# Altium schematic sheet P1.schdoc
size 1117 x 863 mm; Symbol: Drawing-Symbol_A4; @Project Name: WYVERN-E; @Page Count: 1; @Update Date: 2026-08-05; @Create Date: 2026-08-05; @Schematic Name: Schematic1; @Page No: 1; @Page Name: P1; Company: EasyEDA.com; Version: V1.0; Page Size: A4; Device: Drawing-Symbol_A4; @Create Time: 14:42:15; @Update Time: 14:42:15; Border: 1; Width: 4400; Height: 3400; Region Start: 1; X Region Count: 6; Y Region Count: 4; Blade Width: 10; Title Block Position: 3; @Board Name: Board1
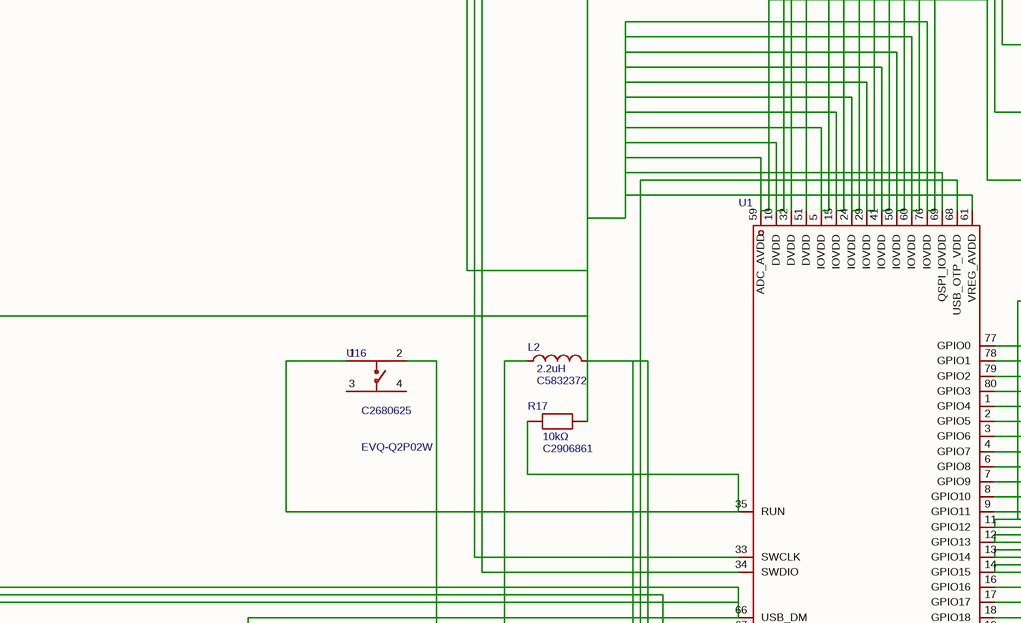
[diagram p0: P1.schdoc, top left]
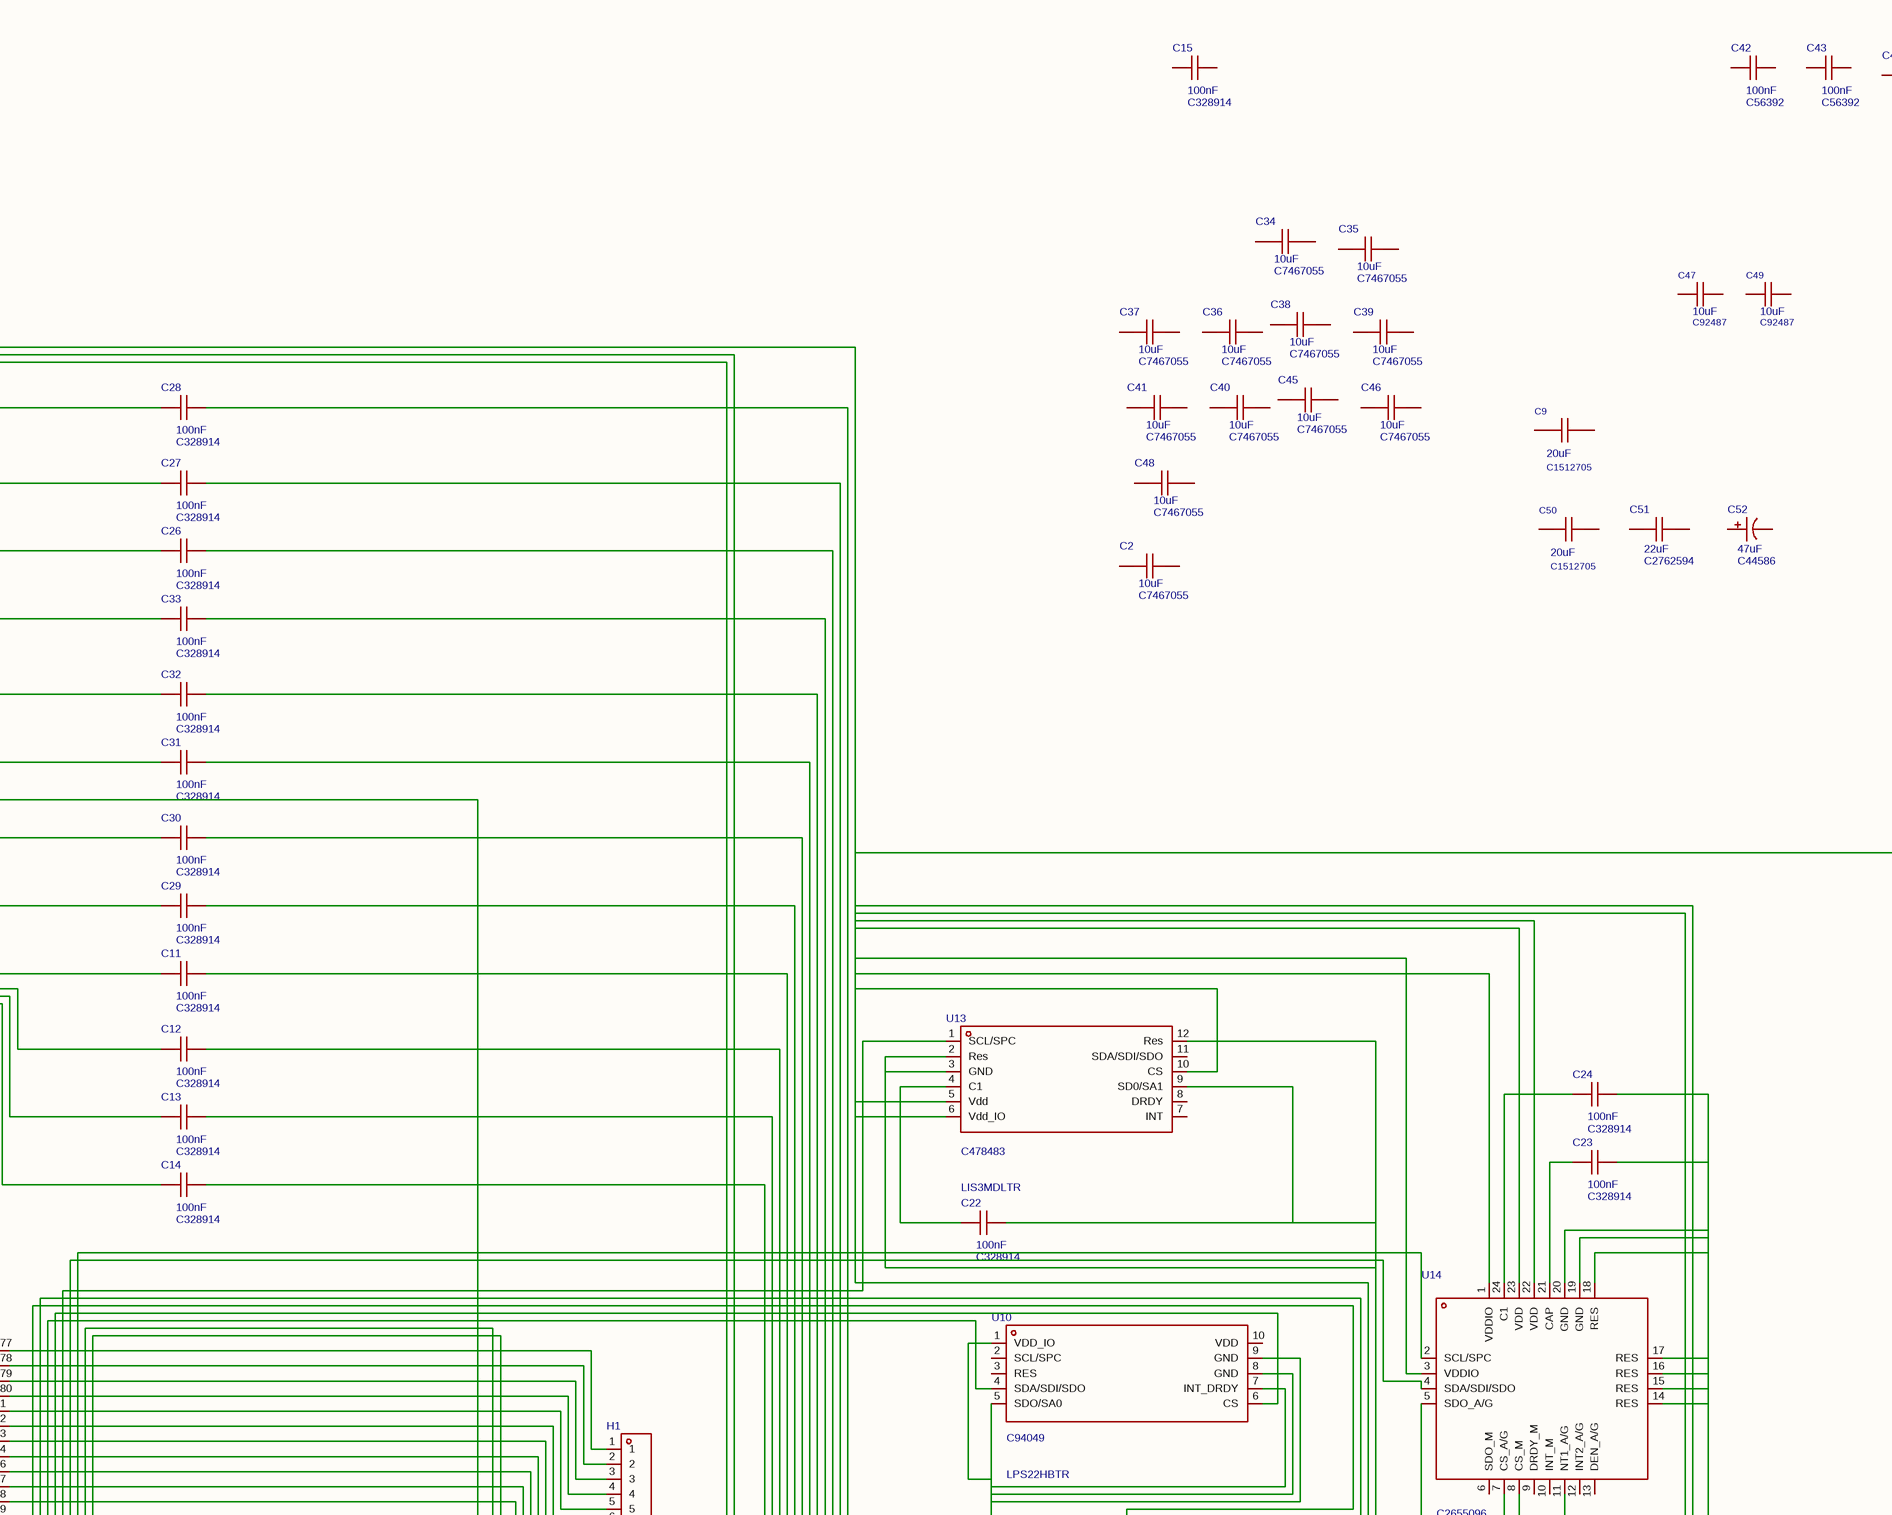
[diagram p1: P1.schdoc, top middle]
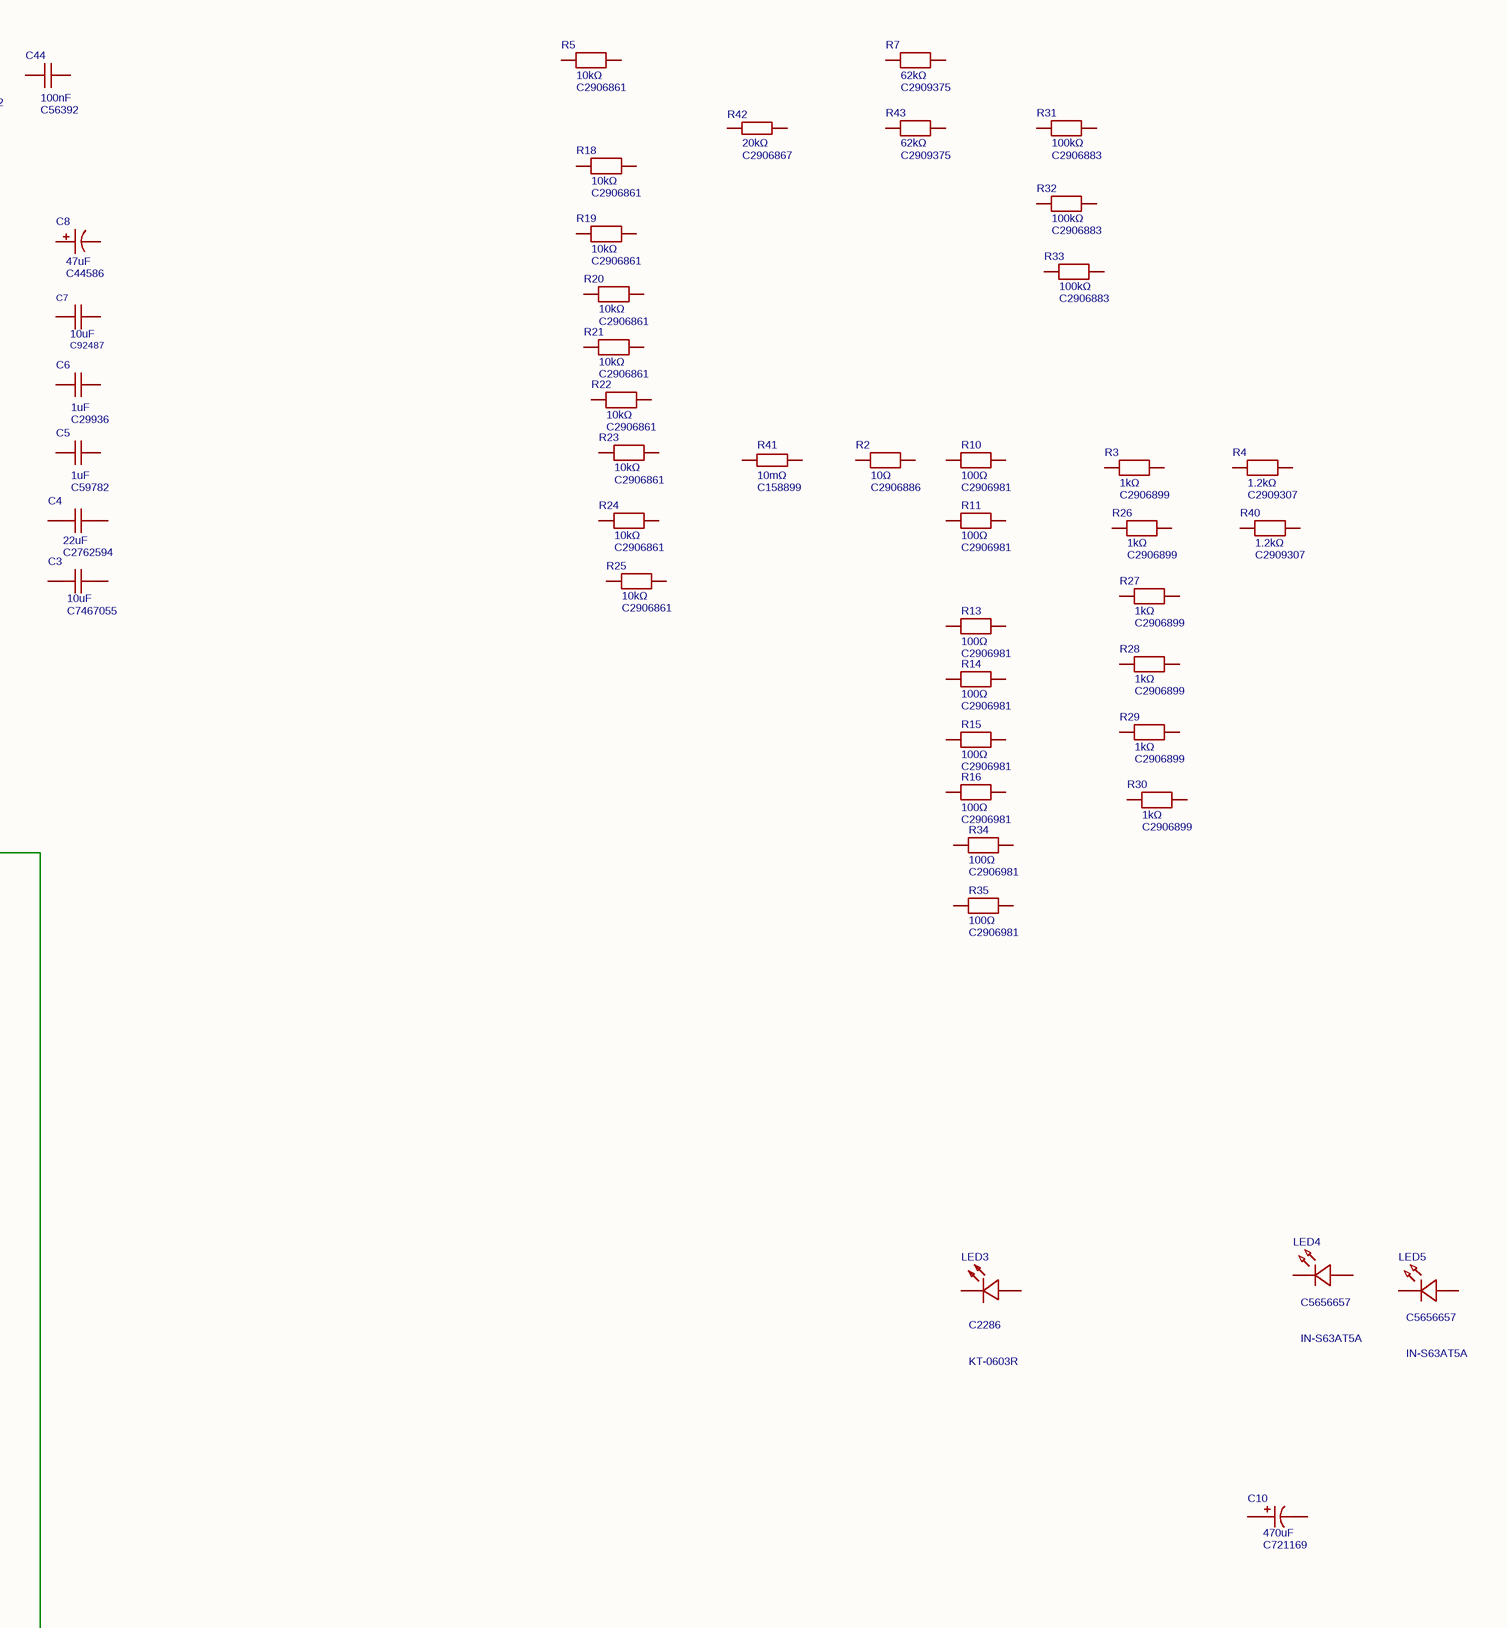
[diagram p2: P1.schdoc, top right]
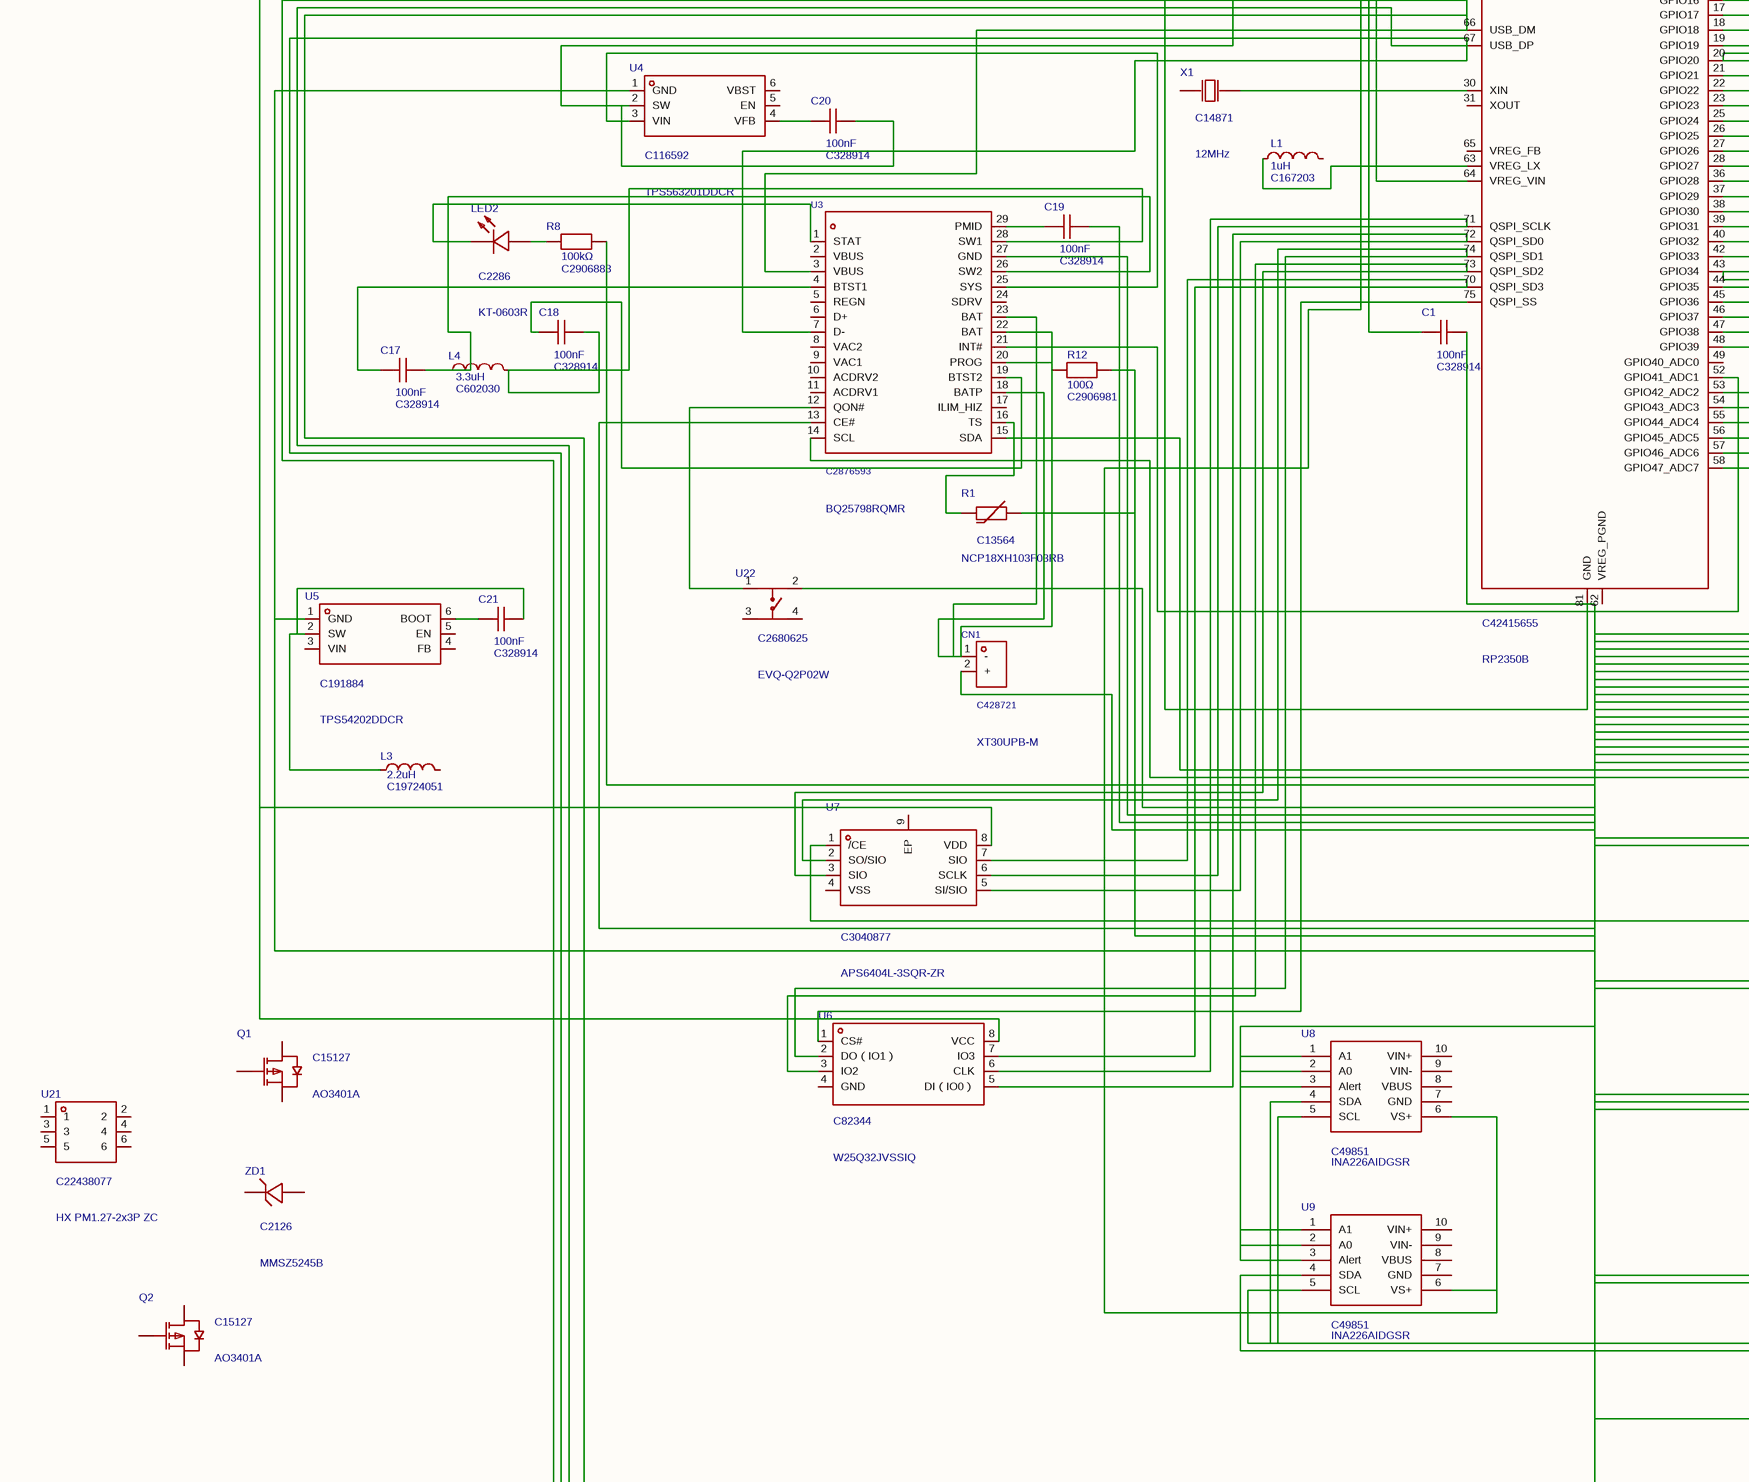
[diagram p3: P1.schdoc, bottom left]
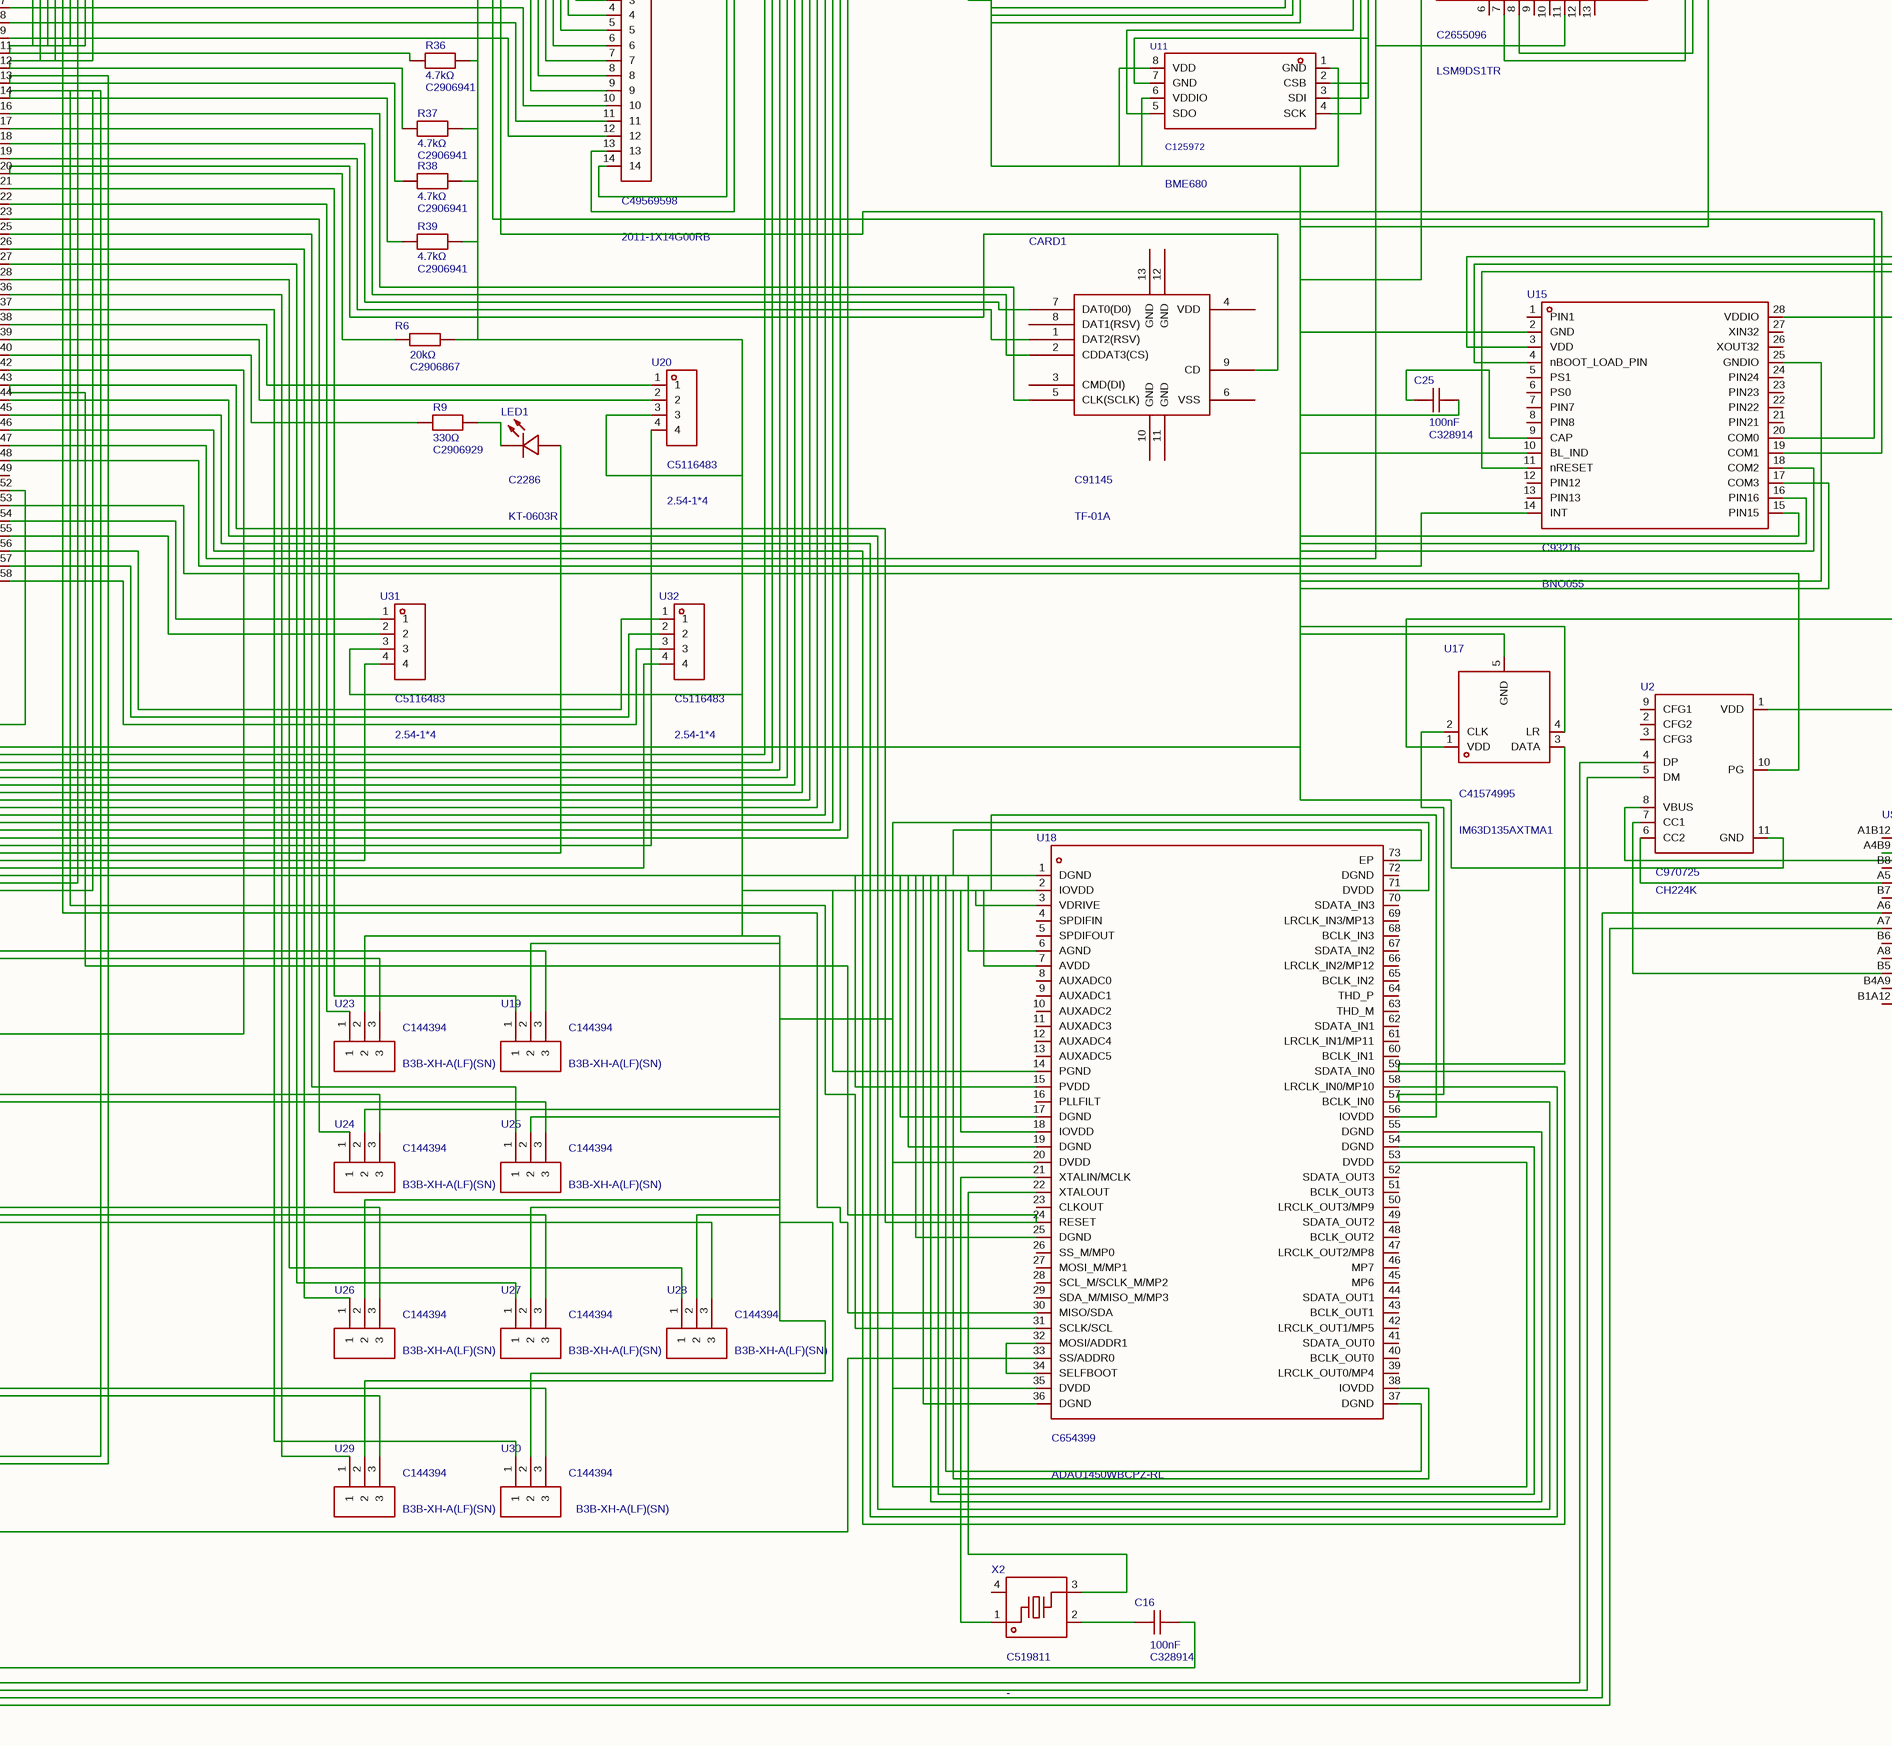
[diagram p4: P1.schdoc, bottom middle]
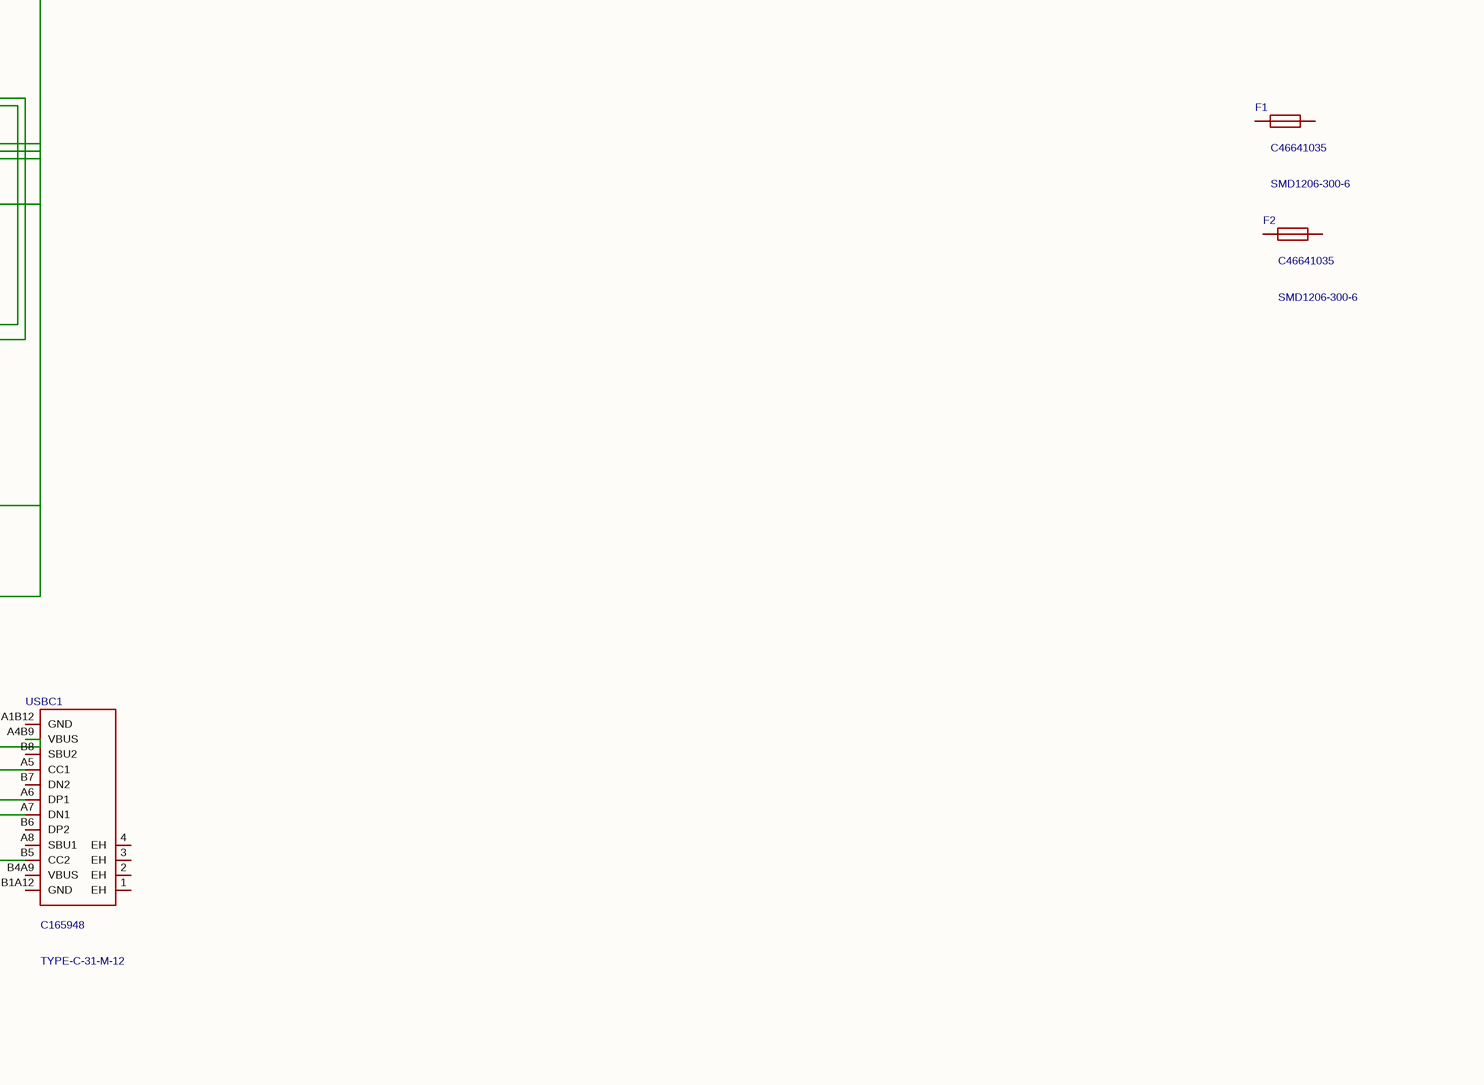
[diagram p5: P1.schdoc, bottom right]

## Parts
C1  100nF  Supplier Part: C328914  [C0402]
C2  10uF  Supplier Part: C7467055  [C0603]
C3  10uF  Supplier Part: C7467055  [C0603]
C4  22uF  Supplier Part: C2762594  [C0603]
C5  1uF  Supplier Part: C59782  [C0603]
C6  1uF  Supplier Part: C29936  [C0603]
C7  10uF  Supplier Part: C92487  [C0603]
C8  47uF  Supplier Part: C44586  [CAP-TH_BD5.0-P2.00-D0.8-FD]
C9  20uF  Supplier Part: C1512705  [C1812]
C10  470uF  Supplier Part: C721169  [CAP-TH_BD8.0-P3.50-D0.6-FD]
C11  100nF  Supplier Part: C328914  [C0402]
C12  100nF  Supplier Part: C328914  [C0402]
C13  100nF  Supplier Part: C328914  [C0402]
C14  100nF  Supplier Part: C328914  [C0402]
C15  100nF  Supplier Part: C328914  [C0402]
C16  100nF  Supplier Part: C328914  [C0402]
C17  100nF  Supplier Part: C328914  [C0402]
C18  100nF  Supplier Part: C328914  [C0402]
C19  100nF  Supplier Part: C328914  [C0402]
C20  100nF  Supplier Part: C328914  [C0402]
C21  100nF  Supplier Part: C328914  [C0402]
C22  100nF  Supplier Part: C328914  [C0402]
C23  100nF  Supplier Part: C328914  [C0402]
C24  100nF  Supplier Part: C328914  [C0402]
C25  100nF  Supplier Part: C328914  [C0402]
C26  100nF  Supplier Part: C328914  [C0402]
C27  100nF  Supplier Part: C328914  [C0402]
C28  100nF  Supplier Part: C328914  [C0402]
C29  100nF  Supplier Part: C328914  [C0402]
C30  100nF  Supplier Part: C328914  [C0402]
C31  100nF  Supplier Part: C328914  [C0402]
C32  100nF  Supplier Part: C328914  [C0402]
C33  100nF  Supplier Part: C328914  [C0402]
C34  10uF  Supplier Part: C7467055  [C0603]
C35  10uF  Supplier Part: C7467055  [C0603]
C36  10uF  Supplier Part: C7467055  [C0603]
C37  10uF  Supplier Part: C7467055  [C0603]
C38  10uF  Supplier Part: C7467055  [C0603]
C39  10uF  Supplier Part: C7467055  [C0603]
C40  10uF  Supplier Part: C7467055  [C0603]
C41  10uF  Supplier Part: C7467055  [C0603]
C42  100nF  Supplier Part: C56392  [C0402]
C43  100nF  Supplier Part: C56392  [C0402]
C44  100nF  Supplier Part: C56392  [C0402]
C45  10uF  Supplier Part: C7467055  [C0603]
C46  10uF  Supplier Part: C7467055  [C0603]
C47  10uF  Supplier Part: C92487  [C0603]
C48  10uF  Supplier Part: C7467055  [C0603]
C49  10uF  Supplier Part: C92487  [C0603]
C50  20uF  Supplier Part: C1512705  [C1812]
C51  22uF  Supplier Part: C2762594  [C0603]
C52  47uF  Supplier Part: C44586  [CAP-TH_BD5.0-P2.00-D0.8-FD]
CARD1  TF-01A  Supplier Part: C91145  [TF-SMD_TF-01A]
CN1  XT30UPB-M  Supplier Part: C428721  [CONN-TH_XT30UPB-M]
F1  SMD1206-300-6  Supplier Part: C46641035  [F1206]
F2  SMD1206-300-6  Supplier Part: C46641035  [F1206]
H1  2011-1X14G00RB  Supplier Part: C49569598  [HDR-TH_14P-P2.54-H-M-W6.0-N]
L1  1uH  Supplier Part: C167203  [IND-SMD_L4.4-W4.2]
L2  2.2uH  Supplier Part: C5832372  [IND-SMD_L2.5-W2.0_MHCHL2520]
L3  2.2uH  Supplier Part: C19724051  [IND-SMD_L5.5-W5.2_NBMC0530N]
L4  3.3uH  Supplier Part: C602030  [IND-SMD_L4.0-W4.0]
LED1  KT-0603R  Supplier Part: C2286  [LED-SMD_L1.6-W0.8-R-RD]
LED2  KT-0603R  Supplier Part: C2286  [LED-SMD_L1.6-W0.8-R-RD]
LED3  KT-0603R  Supplier Part: C2286  [LED-SMD_L1.6-W0.8-R-RD]
LED4  IN-S63AT5A  Supplier Part: C5656657  [LED0603-RD]
LED5  IN-S63AT5A  Supplier Part: C5656657  [LED0603-RD]
Q1  AO3401A  Supplier Part: C15127  [SOT-23_L2.9-W1.3-P1.90-LS2.4-BR]
Q2  AO3401A  Supplier Part: C15127  [SOT-23_L2.9-W1.3-P1.90-LS2.4-BR]
R1  NCP18XH103F03RB  Supplier Part: C13564  [R0603]
R2  10Ω  Supplier Part: C2906886  [R0402]
R3  1kΩ  Supplier Part: C2906899  [R0402]
R4  1.2kΩ  Supplier Part: C2909307  [R0402]
R5  10kΩ  Supplier Part: C2906861  [R0402]
R6  20kΩ  Supplier Part: C2906867  [R0402]
R7  62kΩ  Supplier Part: C2909375  [R0402]
R8  100kΩ  Supplier Part: C2906883  [R0402]
R9  330Ω  Supplier Part: C2906929  [R0402]
R10  100Ω  Supplier Part: C2906981  [R0603]
R11  100Ω  Supplier Part: C2906981  [R0603]
R12  100Ω  Supplier Part: C2906981  [R0603]
R13  100Ω  Supplier Part: C2906981  [R0603]
R14  100Ω  Supplier Part: C2906981  [R0603]
R15  100Ω  Supplier Part: C2906981  [R0603]
R16  100Ω  Supplier Part: C2906981  [R0603]
R17  10kΩ  Supplier Part: C2906861  [R0402]
R18  10kΩ  Supplier Part: C2906861  [R0402]
R19  10kΩ  Supplier Part: C2906861  [R0402]
R20  10kΩ  Supplier Part: C2906861  [R0402]
R21  10kΩ  Supplier Part: C2906861  [R0402]
R22  10kΩ  Supplier Part: C2906861  [R0402]
R23  10kΩ  Supplier Part: C2906861  [R0402]
R24  10kΩ  Supplier Part: C2906861  [R0402]
R25  10kΩ  Supplier Part: C2906861  [R0402]
R26  1kΩ  Supplier Part: C2906899  [R0402]
R27  1kΩ  Supplier Part: C2906899  [R0402]
R28  1kΩ  Supplier Part: C2906899  [R0402]
R29  1kΩ  Supplier Part: C2906899  [R0402]
R30  1kΩ  Supplier Part: C2906899  [R0402]
R31  100kΩ  Supplier Part: C2906883  [R0402]
R32  100kΩ  Supplier Part: C2906883  [R0402]
R33  100kΩ  Supplier Part: C2906883  [R0402]
R34  100Ω  Supplier Part: C2906981  [R0603]
R35  100Ω  Supplier Part: C2906981  [R0603]
R36  4.7kΩ  Supplier Part: C2906941  [R0402]
R37  4.7kΩ  Supplier Part: C2906941  [R0402]
R38  4.7kΩ  Supplier Part: C2906941  [R0402]
R39  4.7kΩ  Supplier Part: C2906941  [R0402]
R40  1.2kΩ  Supplier Part: C2909307  [R0402]
R41  10mΩ  Supplier Part: C158899  [R0603]
R42  20kΩ  Supplier Part: C2906867  [R0402]
R43  62kΩ  Supplier Part: C2909375  [R0402]
U1  RP2350B  Supplier Part: C42415655  [QFN-80_L10.0-W10.0-P0.40-TL-EP3.4]
U2  CH224K  Supplier Part: C970725  [ESSOP-10_L4.9-W3.9-P1.0-LS6.0-TL-EP]
U3  BQ25798RQMR  Supplier Part: C2876593  [QFN-29_L4.0-W4.0-P0.40-TL-BQ25792RQMR]
U4  TPS563201DDCR  Supplier Part: C116592  [SOT-23-6_L2.9-W1.6-P0.95-LS2.8-BR]
U5  TPS54202DDCR  Supplier Part: C191884  [SOT-23-6_L2.9-W1.6-P0.95-LS2.8-BL]
U6  W25Q32JVSSIQ  Supplier Part: C82344  [SOIC-8_L5.3-W5.3-P1.27-LS8.0-BL]
U7  APS6404L-3SQR-ZR  Supplier Part: C3040877  [USON-8_L3.0-W2.0-P0.50-BL-EP]
U8  INA226AIDGSR  Supplier Part: C49851  [MSOP-10_L3.0-W3.0-P0.50-LS5.0-BL]
U9  INA226AIDGSR  Supplier Part: C49851  [MSOP-10_L3.0-W3.0-P0.50-LS5.0-BL]
U10  LPS22HBTR  Supplier Part: C94049  [HLGA-10L_LPS22HBTR]
U11  BME680  Supplier Part: C125972  [LGA-8_L3.0-W3.0-P0.80-TR]
U13  LIS3MDLTR  Supplier Part: C478483  [LGA-12_L2.0-W2.0-P0.50-BL]
U14  LSM9DS1TR  Supplier Part: C2655096  [LGA-24_L3.5-W3.0-P0.43-TL]
U15  BNO055  Supplier Part: C93216  [LGA-28_L5.2-W3.8-P0.50-BL]
U16  EVQ-Q2P02W  Supplier Part: C2680625  [SW-SMD_4P-L6.5-W6.0-P4.00-LS6.6-TL]
U17  IM63D135AXTMA1  Supplier Part: C41574995  [MIC-SMD_5P-L3.5-W2.7_IM66D130AXTMA1]
U18  ADAU1450WBCPZ-RL  Supplier Part: C654399  [LFCSP-72_L10.0-W9.8-P0.50-LS10.2-TL-EP5.5]
U19  B3B-XH-A(LF)(SN)  Supplier Part: C144394  [CONN-TH_3P-P2.50_A2501WV2-3P]
U20  2.54-1*4  Supplier Part: C5116483  [HDR-TH_4P-P2.54-V-M-1]
U21  HX PM1.27-2x3P ZC  Supplier Part: C22438077  [HDR-TH_6P-HX-PM1.27-2X3P-ZC]
U22  EVQ-Q2P02W  Supplier Part: C2680625  [SW-SMD_4P-L6.5-W6.0-P4.00-LS6.6-TL]
U23  B3B-XH-A(LF)(SN)  Supplier Part: C144394  [CONN-TH_3P-P2.50_A2501WV2-3P]
U24  B3B-XH-A(LF)(SN)  Supplier Part: C144394  [CONN-TH_3P-P2.50_A2501WV2-3P]
U25  B3B-XH-A(LF)(SN)  Supplier Part: C144394  [CONN-TH_3P-P2.50_A2501WV2-3P]
U26  B3B-XH-A(LF)(SN)  Supplier Part: C144394  [CONN-TH_3P-P2.50_A2501WV2-3P]
U27  B3B-XH-A(LF)(SN)  Supplier Part: C144394  [CONN-TH_3P-P2.50_A2501WV2-3P]
U28  B3B-XH-A(LF)(SN)  Supplier Part: C144394  [CONN-TH_3P-P2.50_A2501WV2-3P]
U29  B3B-XH-A(LF)(SN)  Supplier Part: C144394  [CONN-TH_3P-P2.50_A2501WV2-3P]
U30  B3B-XH-A(LF)(SN)  Supplier Part: C144394  [CONN-TH_3P-P2.50_A2501WV2-3P]
U31  2.54-1*4  Supplier Part: C5116483  [HDR-TH_4P-P2.54-V-M-1]
U32  2.54-1*4  Supplier Part: C5116483  [HDR-TH_4P-P2.54-V-M-1]
USBC1  TYPE-C-31-M-12  Supplier Part: C165948  [USB-C_SMD-TYPE-C-31-M-12_1]
X1  12MHz  Supplier Part: C14871  [HC-49S_L11.4-W4.8]
X2  -  Supplier Part: C519811  [CRYSTAL-SMD_4P-L3.2-W2.5-BL]
ZD1  MMSZ5245B  Supplier Part: C2126  [SOD-123_L2.8-W1.8-LS3.7-RD]

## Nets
NetC1_1: C1.1 U1.68(USB_OTP_VDD)
NetC1_2: C1.2 C11.2 C12.2 C13.2 C14.2 C16.2 C19.2 C23.2 C24.2 C25.2 C26.2 C27.2 C28.2 C29.2 C30.2 C31.2 C32.2 C33.2 CN1.2(+) LED1.1(A) R1.2 R8.2 R12.2 U1.81(GND) U2.11(GND) U3.13(CE#) U3.27(GND) U4.1(GND) U5.1(GND) U8.1(A1) U8.2(A0) U8.3(Alert) U9.1(A1) U9.2(A0) U9.3(Alert) U10.1(VDD_IO) U10.5(SDO/SA0) U10.7(INT_DRDY) U10.8(GND) U10.9(GND) U11.1(GND) U11.6(VDDIO) U11.8(VDD) U14.5(SDO_A/G) U14.14(RES) U14.15(RES) U14.16(RES) U14.17(RES) U14.18(RES) U14.19(GND) U14.20(GND) U15.2(GND) U15.10(BL_IND) U15.15(PIN15) U15.16(PIN16) U15.17(COM3) U15.18(COM2) U15.25(GNDIO) U16.2 U17.4(LR) U17.5(GND) U18.1(DGND) U18.6(AGND) U18.15(PVDD) U18.17(DGND) U18.19(DGND) U18.25(DGND) U18.32(MOSI/ADDR1) U18.33(SS/ADDR0) U18.34(SELFBOOT) U18.36(DGND) U18.37(DGND) U18.54(DGND) U18.55(DGND) U18.73(EP) U19.3 U20.4 U22.2 U23.3 U24.3 U25.3 U26.3 U27.3 U28.3 U29.3 U30.3 U31.4 U32.4
NetC11_1: C11.1 C14.1 C26.1 C27.1 C28.1 C29.1 C30.1 C31.1 C32.1 C33.1 L2.2 R6.2 R17.2 R36.2 R37.2 R38.2 R39.2 U1.5(IOVDD) U1.10(DVDD) U1.15(IOVDD) U1.24(IOVDD) U1.29(IOVDD) U1.41(IOVDD) U1.50(IOVDD) U1.59(ADC_AVDD) U1.60(IOVDD) U1.61(VREG_AVDD) U1.64(VREG_VIN) U1.69(QSPI_IOVDD) U1.76(IOVDD) U2.1(VDD) U6.8(VCC) U7.8(VDD) U8.6(VS+) U9.6(VS+) U11.2(CSB) U11.3(SDI) U11.7(GND) U13.5(Vdd) U13.6(Vdd_IO) U13.10(CS) U14.1(VDDIO) U14.3(VDDIO) U14.7(CS_A/G) U14.8(CS_M) U14.22(VDD) U14.23(VDD) U15.3(VDD) U15.4(nBOOT_LOAD_PIN) U15.11(nRESET) U15.28(VDDIO) U17.1(VDD) U18.2(IOVDD) U18.3(VDRIVE) U18.7(AVDD) U18.14(PGND) U18.18(IOVDD) U18.20(DVDD) U18.35(DVDD) U18.38(IOVDD) U18.53(DVDD) U18.56(IOVDD) U18.71(DVDD) U19.2 U20.3 U23.2 U24.2 U25.2 U26.2 U27.2 U28.2 U29.2 U30.2 U31.3
NetC12_1: C12.1 U1.32(DVDD)
NetC13_1: C13.1 U1.51(DVDD)
NetC16_1: C16.1 X2.2(GND)
NetC17_1: C17.1 U3.4(BTST1)
NetC17_2: C17.2 L4.1 U3.26(SW2)
NetC18_1: C18.1 U3.19(BTST2)
NetC18_2: C18.2 L4.2 U3.28(SW1)
NetC19_1: C19.1 U3.29(PMID)
NetC20_1: C20.1 U4.4(VFB)
NetC20_2: C20.2 L2.1 U4.2(SW)
NetC21_1: C21.1 U5.6(BOOT)
NetC21_2: C21.2 L3.1 U5.2(SW)
NetC22_1: C22.1 U13.4(C1)
NetC22_2: C22.2 U1.47(GPIO38) U13.2(Res) U13.3(GND) U13.9(SD0/SA1) U13.12(Res) U14.11(NT1_A/G)
NetC23_1: C23.1 U14.21(CAP)
NetC24_1: C24.1 U14.24(C1)
NetC25_1: C25.1 U15.9(CAP)
NetCARD1_1: CARD1.1(DAT2(RSV)) U1.19(GPIO19)
NetCARD1_2: CARD1.2(CDDAT3(CS)) U1.17(GPIO17)
NetCARD1_5: CARD1.5(CLK(SCLK)) U1.16(GPIO16)
NetCARD1_7: CARD1.7(DAT0(D0)) U1.18(GPIO18)
NetCARD1_9: CARD1.9(CD) R6.1 U1.20(GPIO20)
NetCN1_1: CN1.1(-) R12.1 U3.18(BATP) U3.20(PROG) U3.22(BAT) U3.23(BAT)
NetH1_1: H1.1 U1.77(GPIO0)
NetH1_2: H1.2 U1.78(GPIO1)
NetH1_3: H1.3 U1.79(GPIO2)
NetH1_4: H1.4 U1.80(GPIO3)
NetH1_5: H1.5 U1.1(GPIO4)
NetH1_6: H1.6 U1.2(GPIO5)
NetH1_7: H1.7 U1.3(GPIO6)
NetH1_8: H1.8 U1.4(GPIO7)
NetH1_9: H1.9 U1.6(GPIO8)
NetH1_10: H1.10 U1.7(GPIO9)
NetH1_11: H1.11 R37.1 R38.1 U1.8(GPIO10) U1.12(GPIO13) U1.13(GPIO14) U3.15(SDA) U9.4(SDA) U10.6(CS) U11.4(SCK) U13.1(SCL/SPC) U14.2(SCL/SPC) U15.19(COM1) U18.30(MISO/SDA)
NetH1_12: H1.12 U1.9(GPIO11)
NetH1_13: H1.13 U1.33(SWCLK)
NetH1_14: H1.14 U1.34(SWDIO)
NetL1_1: L1.1 U1.63(VREG_LX)
NetLED1_2: LED1.2(K) R9.2
NetLED2_1: LED2.1(A) R8.1
NetLED2_2: LED2.2(K) U3.1(STAT)
NetR1_1: R1.1 U3.16(TS)
NetR9_1: R9.1 U1.40(GPIO32)
NetR17_1: R17.1 U1.35(RUN) U16.1
NetR36_1: R36.1 U1.11(GPIO12) U10.4(SDA/SDI/SDO) U11.5(SDO) U14.4(SDA/SDI/SDO) U15.20(COM0)
NetR39_1: R39.1 U1.14(GPIO15) U3.14(SCL) U8.4(SDA) U8.5(SCL) U9.5(SCL) U18.31(SCLK/SCL)
NetU1_21: U1.21(GPIO21) U19.1
NetU1_22: U1.22(GPIO22) U23.1
NetU1_23: U1.23(GPIO23) U24.1
NetU1_25: U1.25(GPIO24) U25.1
NetU1_26: U1.26(GPIO25) U26.1
NetU1_27: U1.27(GPIO26) U27.1
NetU1_28: U1.28(GPIO27) U28.1
NetU1_30: U1.30(XIN) X1.1(OSC1)
NetU1_36: U1.36(GPIO28) U29.1
NetU1_37: U1.37(GPIO29) U30.1
NetU1_38: U1.38(GPIO30) U20.1
NetU1_39: U1.39(GPIO31) U20.2
NetU1_42: U1.42(GPIO33) U7.1(/CE)
NetU1_43: U1.43(GPIO34) U18.24(RESET)
NetU1_44: U1.44(GPIO35) U17.2(CLK) U18.57(BCLK_IN0)
NetU1_45: U1.45(GPIO36) U18.58(LRCLK_IN0/MP10)
NetU1_46: U1.46(GPIO37) U17.3(DATA) U18.59(SDATA_IN0)
NetU1_48: U1.48(GPIO39) U15.14(INT)
NetU1_52: U1.52(GPIO41_ADC1) U3.21(INT#)
NetU1_53: U1.53(GPIO42_ADC2) U2.10(PG)
NetU1_54: U1.54(GPIO43_ADC3) U31.1
NetU1_55: U1.55(GPIO44_ADC4) U31.2
NetU1_56: U1.56(GPIO45_ADC5) U32.1
NetU1_57: U1.57(GPIO46_ADC6) U32.2
NetU1_58: U1.58(GPIO47_ADC7) U32.3
NetU1_66: U1.66(USB_DM) U2.4(DP) U3.3(VBUS) USBC1.A7(DN1)
NetU1_67: U1.67(USB_DP) U2.5(DM) U3.7(D-) USBC1.A6(DP1)
NetU1_70: U1.70(QSPI_SD3) U6.7(IO3) U7.7(SIO)
NetU1_71: U1.71(QSPI_SCLK) U6.6(CLK) U7.6(SCLK)
NetU1_72: U1.72(QSPI_SD0) U6.5(DI（IO0）) U7.5(SI/SIO)
NetU1_73: U1.73(QSPI_SD2) U6.3(IO2) U7.3(SIO)
NetU1_74: U1.74(QSPI_SD1) U6.2(DO（IO1）) U7.2(SO/SIO)
NetU1_75: U1.75(QSPI_SS) U6.1(CS#)
NetU2_6: U2.6(CC2) USBC1.A5(CC1)
NetU2_7: U2.7(CC1) USBC1.B5(CC2)
NetU2_8: U2.8(VBUS) USBC1.A4B9(VBUS)
NetU3_12: U3.12(QON#) U22.1
NetU3_25: U3.25(SYS) U4.3(VIN)
NetU18_21: U18.21(XTALIN/MCLK) X2.1
NetU18_22: U18.22(XTALOUT) X2.3

Not connected (* = marked no-connect by the designer): C2 1 2; C3 1 2; C4 1 2; C5 1 2; C6 1 2; C7 1 2; C8 1 2; C9 1 2; C10 1 2; C15 1 2; C34 1 2; C35 1 2; C36 1 2; C37 1 2; C38 1 2; C39 1 2; C40 1 2; C41 1 2; C42 1 2; C43 1 2; C44 1 2; C45 1 2; C46 1 2; C47 1 2; C48 1 2; C49 1 2; C50 1 2; C51 1 2; C52 1 2; CARD1 3(CMD(DI)) 4(VDD) 6(VSS) 8(DAT1(RSV)) 10(GND) 11(GND) 12(GND) 13(GND); F1 1 2; F2 1 2; L1 2; L3 2; LED3 1(A) 2(K); LED4 1(C) 2(A); LED5 1(C) 2(A); Q1 1(G) 2(S) 3(D); Q2 1(G) 2(S) 3(D); R2 1 2; R3 1 2; R4 1 2; R5 1 2; R7 1 2; R10 1 2; R11 1 2; R13 1 2; R14 1 2; R15 1 2; R16 1 2; R18 1 2; R19 1 2; R20 1 2; R21 1 2; R22 1 2; R23 1 2; R24 1 2; R25 1 2; R26 1 2; R27 1 2; R28 1 2; R29 1 2; R30 1 2; R31 1 2; R32 1 2; R33 1 2; R34 1 2; R35 1 2; R40 1 2; R41 1 2; R42 1 2; R43 1 2; U1 31(XOUT) 49(GPIO40_ADC0) 62(VREG_PGND) 65(VREG_FB); U2 2(CFG2) 3(CFG3) 9(CFG1); U3 2(VBUS) 5(REGN) 6(D+) 8(VAC2) 9(VAC1) 10(ACDRV2) 11(ACDRV1) 17(ILIM_HIZ) 24(SDRV); U4 5(EN) 6(VBST); U5 3(VIN) 4(FB) 5(EN); U6 4(GND); U7 4(VSS) 9(EP); U8 7(GND) 8(VBUS) 9(VIN-) 10(VIN+); U9 7(GND) 8(VBUS) 9(VIN-) 10(VIN+); U10 2(SCL/SPC) 3(RES) 10(VDD); U13 7(INT) 8(DRDY) 11(SDA/SDI/SDO); U14 6(SDO_M) 9(DRDY_M) 10(INT_M) 12(INT2_A/G) 13(DEN_A/G); U15 1(PIN1) 5(PS1) 6(PS0) 7(PIN7) 8(PIN8) 12(PIN12) 13(PIN13) 21(PIN21) 22(PIN22) 23(PIN23) 24(PIN24) 26(XOUT32) 27(XIN32); U16 3 4; U18 4(SPDIFIN) 5(SPDIFOUT) 8(AUXADC0) 9(AUXADC1) 10(AUXADC2) 11(AUXADC3) 12(AUXADC4) 13(AUXADC5) 16(PLLFILT) 23(CLKOUT) 26(SS_M/MP0) 27(MOSI_M/MP1) 28(SCL_M/SCLK_M/MP2) 29(SDA_M/MISO_M/MP3) 39(LRCLK_OUT0/MP4) 40(BCLK_OUT0) 41(SDATA_OUT0) 42(LRCLK_OUT1/MP5) 43(BCLK_OUT1) 44(SDATA_OUT1) 45(MP6) 46(MP7) 47(LRCLK_OUT2/MP8) 48(BCLK_OUT2) 49(SDATA_OUT2) 50(LRCLK_OUT3/MP9) 51(BCLK_OUT3) 52(SDATA_OUT3) 60(BCLK_IN1) 61(LRCLK_IN1/MP11) 62(SDATA_IN1) 63(THD_M) 64(THD_P) 65(BCLK_IN2) 66(LRCLK_IN2/MP12) 67(SDATA_IN2) 68(BCLK_IN3) 69(LRCLK_IN3/MP13) 70(SDATA_IN3) 72(DGND); U21 1 2 3 4 5 6; U22 3 4; USBC1 1(EH) 2(EH) 3(EH) 4(EH) A1B12(GND) A8(SBU1) B1A12(GND) B4A9(VBUS) B6(DP2) B7(DN2) B8(SBU2); X1 2(OSC2); X2 4(GND); ZD1 1(K) 2(A)

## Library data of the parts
C1 C11-C33 = FN15X104K160PNG: Capacitance:100nF Tolerance:±10% Tolerance:±10% Voltage Rating:16V Temperature Coefficient:X7R; Manufacturer: PSA(信昌电陶); AddInBom: yes; ModelId: b7d13df3e9464d7a99d0651d1a5b4d570819f05c4eef4c71ace90d822a990e87; ModelName: C0402_L1.0-W0.5-H0.5; ModelTransform: 39.37,19.685,0,0,0,0,0,0,0; Tolerance: ±10%; Voltage Rating: 16V; Temperature Coefficient: X7R
C2 C3 C34-C41 C45 C46 C48 = FCC0603X106M250CT: Capacitance:10uF Tolerance:±20% Tolerance:±20% Voltage Rating:25V Temperature Coefficient:X5R; Manufacturer: FOJAN(富捷); AddInBom: yes; ModelId: 624118aa3cc7497086c383c2d72e08520819f05c4eef4c71ace90d822a990e87; ModelName: C0603_L1.6-W0.8-H0.8; ModelTransform: 62.992,31.496,0,0,0,0,0,0,0; Tolerance: ±20%; Voltage Rating: 25V; Temperature Coefficient: X5R
C4 C51 = CL10A226MO7JZNC: Capacitance:22uF Tolerance:±20% Tolerance:±20% Voltage Rating:16V Temperature Coefficient:X5R; Manufacturer: SAMSUNG(三星); AddInBom: yes; ModelId: 624118aa3cc7497086c383c2d72e08520819f05c4eef4c71ace90d822a990e87; ModelName: C0603_L1.6-W0.8-H0.8; ModelTransform: 62.992,31.496,0,0,0,0,0,0,0; Tolerance: ±20%; Voltage Rating: 16V; Temperature Coefficient: X5R
C5 = CL10B105KO8NNNC: Capacitance:1uF Tolerance:±10% Tolerance:±10% Voltage Rating:16V Temperature Coefficient:X7R; Manufacturer: SAMSUNG(三星); AddInBom: yes; ModelId: 624118aa3cc7497086c383c2d72e08520819f05c4eef4c71ace90d822a990e87; ModelName: C0603_L1.6-W0.8-H0.8; ModelTransform: 62.992,31.496,0,0,0,0,0,0,0; Tolerance: ±10%; Voltage Rating: 16V; Temperature Coefficient: X7R
C6 = CL10B105KA8NNNC: Capacitance:1uF Tolerance:±10% Tolerance:±10% Voltage Rating:25V Temperature Coefficient:X7R; Manufacturer: SAMSUNG(三星); AddInBom: yes; ModelId: 624118aa3cc7497086c383c2d72e08520819f05c4eef4c71ace90d822a990e87; ModelName: C0603_L1.6-W0.8-H0.8; ModelTransform: 62.992,31.496,0,0,0,0,0,0,0; Tolerance: ±10%; Voltage Rating: 25V; Temperature Coefficient: X7R
C7 C47 C49 = CL10A106MO8NQNC: Capacitance:10uF Tolerance:±20% Tolerance:±20% Voltage Rating:16V Temperature Coefficient:X5R; Manufacturer: SAMSUNG(三星); AddInBom: yes; ModelId: 624118aa3cc7497086c383c2d72e08520819f05c4eef4c71ace90d822a990e87; ModelName: C0603_L1.6-W0.8-H0.8; ModelTransform: 62.992,31.496,0,0,0,0,0,0,0; Tolerance: ±20%; Voltage Rating: 16V; Temperature Coefficient: X5R
C8 C52 = KS476M025D07RR0VH2FP0: Capacitance:47uF Tolerance:±20% Tolerance:±20% Voltage Rating:25V Pin Spacing:2mm Diameter:5mm Height - Seated (Max):7mm Lifetime:1000hrs@105℃ Operating Temperature:-40℃~+105℃ Operating Temperature:-40℃~+105℃; Manufacturer: Chengx(承兴); Symbol: 47uF 25V 5*7; AddInBom: yes; ModelId: a6753ac7f17a4fce96dd233a0f76b1540819f05c4eef4c71ace90d822a990e87; ModelName: CAP-TH_D5.0×H7.0×P2.0; ModelTransform: 197.091,196.7911,0,0,0,0,0,0,-137.795; Tolerance: ±20%; Voltage Rating: 25V; Pin Spacing: 2mm
C9 C50 = C1812C206K3RLCAUTO: Capacitance:20uF Tolerance:±10% Tolerance:±10% Voltage Rated: Temperature Coefficient:; Manufacturer: KEMET(基美); AddInBom: yes; ModelId: 9490267e11c744c49bc8222b92720aba0819f05c4eef4c71ace90d822a990e87; ModelName: C1812_L4.5-W3.2-H2.6; ModelTransform: 177.165,125.984,0,0,0,0,0.0005,0,0; Tolerance: ±10%
C10 = ERF1EM471F12OT: Capacitance:470uF Tolerance:±20% Tolerance:±20% Voltage Rating:25V Ripple Current:- Equivalent Series Resistance(ESR):- Pin Spacing:3.5mm Diameter:8mm Height - Seated (Max):12mm Lifetime:- Operating Temperature:-40℃~+105℃ Operating Temperature:-40℃~+105℃; Manufacturer: AISHI(艾华集团); AddInBom: yes; ModelId: 26f37486632942dc87f6308ee91e8f400819f05c4eef4c71ace90d822a990e87; ModelName: CAP-TH_D8.0-H8.0-P3.50; ModelTransform: 314.96,314.862,0,180,0,0,0,0,-137.795; Tolerance: ±20%; Voltage Rating: 25V; Pin Spacing: 3.5mm
C42-C44 = 0402B104K250NT: Capacitance:100nF Tolerance:±10% Tolerance:±10% Voltage Rating:25V Temperature Coefficient:X7R; Manufacturer: FH(风华); AddInBom: yes; ModelId: b7d13df3e9464d7a99d0651d1a5b4d570819f05c4eef4c71ace90d822a990e87; ModelName: C0402_L1.0-W0.5-H0.5; ModelTransform: 39.37,19.685,0,0,0,0,0,0,0; Tolerance: ±10%; Voltage Rating: 25V; Temperature Coefficient: X7R
CARD1 = TF-01A_C91145: Card Connection Mode:Push-Push Card Type:MicroSD Card (TF Card) Connector Type:Connector and Ejector Additional Card Detection Pins:- Supplementary Features:With Locating Pins Height Above Board:1.85mm Operating Temperature:- Operating Temperature:-; Manufacturer: 韩国韩荣; Add into BOM: yes; ModelId: 5685a23adc9a4e3e9b914abe5ae03aae0819f05c4eef4c71ace90d822a990e87; ModelTransform: 633.85696,590.65303,0,0,0,0,0,-85.63,-23.622
CN1 = XT30UPB-M: Rated current:15A Rated voltage: colour:Yellow Connector type:Model aircraft plug contact resistance: interface form:Male insulating material: metal material:Gold plating; Manufacturer: AMASS(艾迈斯); Add into BOM: yes; ModelId: 8606296c6a2a4a0aa30f28b26a2c1e3a0819f05c4eef4c71ace90d822a990e87; ModelTransform: 401.574,204.724,0,0,0,0,0,0,-78.74; Rated current: 15A; interface form: Male
F1 F2 = SMD1206-300-6: Voltage - Max:6V Current - Max:40A Hold Current:3A Trip Current:6A Power Dissipation:1W Resistance - Initial (Ri) (Min):10mΩ Resistance - Post Trip (R1) (Max):50mΩ Time to Trip(Max):4s Operating Temperature:-40℃~+85℃ Operating Temperature:-40℃~+85℃ Length; Manufacturer: R+O(宏嘉诚); Add into BOM: yes; ModelId: 61372169742747e19cbd4ac5ee5e48b10819f05c4eef4c71ace90d822a990e87; ModelName: F1206_L3.2-W1.7-H0.6; ModelTransform: 125.984,66.929,0,0,0,0,0,0,0; Voltage - Max: 6V; Current - Max: 40A; Hold Current: 3A; Trip Current: 6A; Power Dissipation: 1W; Resistance - Initial (Ri) (Min): 10mΩ; Resistance - Post Trip (R1) (Max): 50mΩ; Time to Trip(Max): 4s
H1 = 2011-1X14G00RB: Pin Structure:1x14P Pitch:2.54mm Circluar Pins/Square Pins:Pin Header Mounting Type:Right Angle Number of Rows:1 Number of Pins:14P Current Rating:3A Voltage Rating (Max):600V Length of Mating Pin:6mm Insulation Height:2.5mm Length of End Connection Pin:3; Manufacturer: WingTAT(格林柏); Add into BOM: yes; ModelId: 486cde91a464408db3adaf1731e349420819f05c4eef4c71ace90d822a990e87; ModelTransform: 1399.997,336.22,0,0,0,0,0,-118.11,-118.11; Pin Structure: 1x14P; Pitch: 2.54mm; Current Rating: 3A; Voltage Rating (Max): 600V
L1 = FXL0420-1R0-M: Inductance:1uH Tolerance:±20% Tolerance:±20% Current Rating:6A Current - Saturation(Isat):7A DC Resistance(DCR):27mΩ Type:Molded Inductor; Manufacturer: cjiang(长江微电); AddInBom: yes; ModelId: 202f222253c645ab9b4a671ae12ae5590819f05c4eef4c71ace90d822a990e87; ModelName: IND-SMD_L4.2-W4.4-H2.0; ModelTransform: 173.228,165.354,0,0,0,0,0,0,0; Tolerance: ±20%; Current Rating: 6A; Current - Saturation(Isat): 7A; DC Resistance(DCR): 27mΩ
L2 = FTC252012S2R2MBCA: Inductance:2.2uH Tolerance:±20% Tolerance:±20% Current Rating:3A Current - Saturation(Isat):3.8A DC Resistance(DCR):55mΩ Type:-; Manufacturer: cjiang(长江微电); AddInBom: yes; ModelId: 6030ee72033e42b3943c7a42b03bf5750819f05c4eef4c71ace90d822a990e87; ModelTransform: 98.425,78.74,0,0,0,0,0,0,0; Tolerance: ±20%; Current Rating: 3A; Current - Saturation(Isat): 3.8A; DC Resistance(DCR): 55mΩ
L3 = CY0530AT125DS-2R2MCY: Inductance:2.2uH Tolerance:±20% Tolerance:±20% Current Rating:6A Current - Saturation(Isat):6.7A DC Resistance(DCR):17.3mΩ Type:- Ratings:-; Manufacturer: Sumida(胜美达); AddInBom: yes; Tolerance: ±20%; Current Rating: 6A; Current - Saturation(Isat): 6.7A; DC Resistance(DCR): 17.3mΩ
L4 = FHD4020S-3R3MT: Inductance:3.3uH Tolerance:±20% Tolerance:±20% Current Rating:4A Current - Saturation(Isat):5.9A DC Resistance(DCR):73mΩ Type:Winding Inductor; Manufacturer: cjiang(长江微电); AddInBom: yes; ModelId: eb765a5a931c40af9a8ef05b08821f350819f05c4eef4c71ace90d822a990e87; ModelName: IND-SMD_L4.0-W4.0-H1.9; ModelTransform: 157.48,157.484,0,0,0,0,0,0,0; Tolerance: ±20%; Current Rating: 4A; Current - Saturation(Isat): 5.9A; DC Resistance(DCR): 73mΩ
LED1-LED3 = KT-0603R: Lamp Holder Type:1.6mm x 0.8mm square LED Illumination Color:Red Voltage - Forward(Vf):1.8V~2.4V Voltage - Forward(Vf):1.8V~2.4V Power(Watts):40mW Forward Current:20mA Wavelength - Dominant:615nm~630nm Wavelength - Dominant:615nm~630nm Peak Wavelength:645; Manufacturer: KENTO; Add into BOM: yes; ModelId: 19cc79473bbc420a8203ad67d1a57d420819f05c4eef4c71ace90d822a990e87; ModelName: LED0603_L1.6-W0.8-H0.6; ModelTransform: 63.7794,31.496,0,0,0,0,0,0,0; Illumination Color: Red; Power(Watts): 40mW; Forward Current: 20mA; Peak Wavelength: 645nm; Diode Configuration: Discrete Diode; Lens Color: Water Clear; Luminous Intensity: 300mcd; Viewing Angle: 120°
LED4 LED5 = IN-S63AT5A: Lamp Holder Type:- Illumination Color:Amber Voltage - Forward(Vf):2V Voltage - Forward(Vf):2V Power(Watts):75mW Forward Current:5mA Wavelength - Dominant:605nm Wavelength - Dominant:605nm Peak Wavelength:609nm Diode Configuration:Discrete Diode Lens Color; Manufacturer: Inolux; Add into BOM: yes; ModelId: 5e3b568068dd46cf8019c1d1baa0031b0819f05c4eef4c71ace90d822a990e87; ModelTransform: 63.7794,32.283,0,0,0,0,0,0,0; Illumination Color: Amber; Voltage - Forward(Vf): 2V; Power(Watts): 75mW; Forward Current: 5mA; Wavelength - Dominant: 605nm; Peak Wavelength: 609nm; Lens Color: Water Clear; Luminous Intensity: 35mcd; Viewing Angle: 120°
Q1 Q2 = AO3401A_C15127: Number:1 P-Channel Drain to Source Voltage:30V Current - Continuous Drain(Id):4A RDS(on):47mΩ@10V；85mΩ@2.5V；60mΩ@4.5V Pd - Power Dissipation:- Gate Threshold Voltage (Vgs(th)):900mV Gate Charge(Qg):14nC@10V Input Capacitance(Ciss):645pF Reverse Transfer C; Manufacturer: AOS; Add into BOM: yes; ModelId: 62a57c6760504a01965db6419a6d07df0819f05c4eef4c71ace90d822a990e87; ModelName: SOT-23-3P_L2.9-W1.3-H1.0-LS2.4-P0.95; ModelTransform: 98.64468,114.173,0,180,0,0,0.001,-0.002,0; Drain to Source Voltage: 30V; Current - Continuous Drain(Id): 4A; Gate Threshold Voltage (Vgs(th)): 900mV; Input Capacitance(Ciss): 645pF; Reverse Transfer Capacitance (Crss@Vds): 55pF; Output Capacitance(Coss): 80pF
R1 = NCP18XH103F03RB: Power(Watts):100mW Resistance @ 25℃:10kΩ Resistance Tolerance:±1% Resistance Tolerance:±1% B Constant Tolerance:±1% B Constant (25℃/50℃):3380K B Constant (25℃/75℃):- B Constant (25℃/85℃):3434K B Constant (25℃/100℃):3455K Steady State Current (Max):310uA D; Manufacturer: muRata(村田); Add into BOM: yes; ModelId: 112863783b5b41f1b5254f87eedc79320819f05c4eef4c71ace90d822a990e87; ModelTransform: 31.8897,63.7794,0,90,0,0,0,0,0; Power(Watts): 100mW; Resistance @ 25℃: 10kΩ; Resistance Tolerance: ±1%; B Constant (25℃/50℃): 3380K; B Constant (25℃/85℃): 3434K; B Constant (25℃/100℃): 3455K; Steady State Current (Max): 310uA; Dissipation Factor: 1mW/℃
R2 = FRC0402J100 TS: Type:Thick Film Resistor Resistance:10Ω Tolerance:±5% Tolerance:±5% Power(Watts):62.5mW Voltage-Supply(Max):50V Temperature Coefficient:±200ppm/℃ Temperature Coefficient:±200ppm/℃ Operating Temperature:-55℃~+155℃ Operating Temperature:-55℃~+155℃; Manufacturer: FOJAN(富捷); AddInBom: yes; ModelId: efdecb7dae4442949d28eecaf748420f0819f05c4eef4c71ace90d822a990e87; ModelName: R0402_L1.0-W0.5-H0.4; ModelTransform: 39.37,19.685,0,0,0,0,0,0,0; Tolerance: ±5%; Power(Watts): 62.5mW; Voltage-Supply(Max): 50V
R3 R26-R30 = FRC0402J102 TS: Type:Thick Film Resistor Resistance:1kΩ Tolerance:±5% Tolerance:±5% Power(Watts):62.5mW Voltage-Supply(Max):50V Temperature Coefficient:±100ppm/℃ Temperature Coefficient:±100ppm/℃ Operating Temperature:-55℃~+155℃ Operating Temperature:-55℃~+155℃; Manufacturer: FOJAN(富捷); AddInBom: yes; ModelId: efdecb7dae4442949d28eecaf748420f0819f05c4eef4c71ace90d822a990e87; ModelName: R0402_L1.0-W0.5-H0.4; ModelTransform: 39.37,19.685,0,0,0,0,0,0,0; Tolerance: ±5%; Power(Watts): 62.5mW; Voltage-Supply(Max): 50V
R4 R40 = FRC0402F1201TS: Type:Thick Film Resistor Resistance:1.2kΩ Tolerance:±1% Tolerance:±1% Power(Watts):62.5mW Voltage-Supply(Max):50V Temperature Coefficient:±100ppm/℃ Temperature Coefficient:±100ppm/℃ Operating Temperature:-55℃~+155℃ Operating Temperature:-55℃~+155℃; Manufacturer: FOJAN(富捷); AddInBom: yes; ModelId: efdecb7dae4442949d28eecaf748420f0819f05c4eef4c71ace90d822a990e87; ModelName: R0402_L1.0-W0.5-H0.4; ModelTransform: 39.37,19.685,0,0,0,0,0,0,0; Tolerance: ±1%; Power(Watts): 62.5mW; Voltage-Supply(Max): 50V
R5 R17-R25 = FRC0402F1002TS: Type:Thick Film Resistor Resistance:10kΩ Tolerance:±1% Tolerance:±1% Power(Watts):62.5mW Voltage-Supply(Max):50V Temperature Coefficient:±100ppm/℃ Temperature Coefficient:±100ppm/℃ Operating Temperature:-55℃~+155℃ Operating Temperature:-55℃~+155℃; Manufacturer: FOJAN(富捷); AddInBom: yes; ModelId: efdecb7dae4442949d28eecaf748420f0819f05c4eef4c71ace90d822a990e87; ModelName: R0402_L1.0-W0.5-H0.4; ModelTransform: 39.37,19.685,0,0,0,0,0,0,0; Tolerance: ±1%; Power(Watts): 62.5mW; Voltage-Supply(Max): 50V
R6 R42 = FRC0402F2002TS: Type:Thick Film Resistor Resistance:20kΩ Tolerance:±1% Tolerance:±1% Power(Watts):62.5mW Voltage-Supply(Max):50V Temperature Coefficient:±100ppm/℃ Temperature Coefficient:±100ppm/℃ Operating Temperature:-55℃~+155℃ Operating Temperature:-55℃~+155℃; Manufacturer: FOJAN(富捷); AddInBom: yes; ModelId: efdecb7dae4442949d28eecaf748420f0819f05c4eef4c71ace90d822a990e87; ModelName: R0402_L1.0-W0.5-H0.4; ModelTransform: 39.37,19.685,0,0,0,0,0,0,0; Tolerance: ±1%; Power(Watts): 62.5mW; Voltage-Supply(Max): 50V
R7 R43 = FRC0402F6202TS: Type:Thick Film Resistor Resistance:62kΩ Tolerance:±1% Tolerance:±1% Power(Watts):62.5mW Voltage-Supply(Max):50V Temperature Coefficient:±100ppm/℃ Temperature Coefficient:±100ppm/℃ Operating Temperature:-55℃~+155℃ Operating Temperature:-55℃~+155℃; Manufacturer: FOJAN(富捷); AddInBom: yes; ModelId: efdecb7dae4442949d28eecaf748420f0819f05c4eef4c71ace90d822a990e87; ModelName: R0402_L1.0-W0.5-H0.4; ModelTransform: 39.37,19.685,0,0,0,0,0,0,0; Tolerance: ±1%; Power(Watts): 62.5mW; Voltage-Supply(Max): 50V
R8 R31-R33 = FRC0402J104 TS: Type:Thick Film Resistor Resistance:100kΩ Tolerance:±5% Tolerance:±5% Power(Watts):62.5mW Voltage-Supply(Max):50V Temperature Coefficient:±100ppm/℃ Temperature Coefficient:±100ppm/℃ Operating Temperature:-55℃~+155℃ Operating Temperature:-55℃~+155℃; Manufacturer: FOJAN(富捷); AddInBom: yes; ModelId: efdecb7dae4442949d28eecaf748420f0819f05c4eef4c71ace90d822a990e87; ModelName: R0402_L1.0-W0.5-H0.4; ModelTransform: 39.37,19.685,0,0,0,0,0,0,0; Tolerance: ±5%; Power(Watts): 62.5mW; Voltage-Supply(Max): 50V
R9 = FRC0402J331 TS: Type:Thick Film Resistor Resistance:330Ω Tolerance:±5% Tolerance:±5% Power(Watts):62.5mW Voltage-Supply(Max):50V Temperature Coefficient:±100ppm/℃ Temperature Coefficient:±100ppm/℃ Operating Temperature:-55℃~+155℃ Operating Temperature:-55℃~+155℃; Manufacturer: FOJAN(富捷); AddInBom: yes; ModelId: efdecb7dae4442949d28eecaf748420f0819f05c4eef4c71ace90d822a990e87; ModelName: R0402_L1.0-W0.5-H0.4; ModelTransform: 39.37,19.685,0,0,0,0,0,0,0; Tolerance: ±5%; Power(Watts): 62.5mW; Voltage-Supply(Max): 50V
R10-R16 R34 R35 = FRC0603F1000TS: Type:Thick Film Resistor Resistance:100Ω Tolerance:±1% Tolerance:±1% Power(Watts):100mW Voltage-Supply(Max):75V Temperature Coefficient:±100ppm/℃ Temperature Coefficient:±100ppm/℃ Operating Temperature:-55℃~+155℃ Operating Temperature:-55℃~+155℃; Manufacturer: FOJAN(富捷); AddInBom: yes; ModelId: 112863783b5b41f1b5254f87eedc79320819f05c4eef4c71ace90d822a990e87; ModelTransform: 31.8897,63.7794,0,90,0,0,0,0,0; Tolerance: ±1%; Power(Watts): 100mW; Voltage-Supply(Max): 75V
R36-R39 = FRC0402J472 TS: Type:Thick Film Resistor Resistance:4.7kΩ Tolerance:±5% Tolerance:±5% Power(Watts):62.5mW Voltage-Supply(Max):50V Temperature Coefficient:±100ppm/℃ Temperature Coefficient:±100ppm/℃ Operating Temperature:-55℃~+155℃ Operating Temperature:-55℃~+155℃; Manufacturer: FOJAN(富捷); AddInBom: yes; ModelId: efdecb7dae4442949d28eecaf748420f0819f05c4eef4c71ace90d822a990e87; ModelName: R0402_L1.0-W0.5-H0.4; ModelTransform: 39.37,19.685,0,0,0,0,0,0,0; Tolerance: ±5%; Power(Watts): 62.5mW; Voltage-Supply(Max): 50V
R41 = RTT03R010FTP: Type:Thick Film Resistor Resistance:10mΩ Tolerance:±1% Tolerance:±1% Power(Watts):100mW Temperature Coefficient:±1500ppm/℃ Temperature Coefficient:±1500ppm/℃ Operating Temperature:-55℃~+155℃ Operating Temperature:-55℃~+155℃; Manufacturer: RALEC(旺诠); AddInBom: yes; ModelId: 112863783b5b41f1b5254f87eedc79320819f05c4eef4c71ace90d822a990e87; ModelTransform: 31.8897,63.7794,0,90,0,0,0,0,0; Tolerance: ±1%; Power(Watts): 100mW
U1 = RP2350B_C42415655: Number of I/O:48 Features:Independent watchdog (IWDG)；Power-on reset (POR)；True random number generator (TRNG)；Watchdog reset；Built-in general-purpose timer；Hardware ECC check；External pin reset (NRST)；Integrated LDO; Manufacturer: Raspberry Pi(树莓派); Add into BOM: yes; ModelId: 9f007f8a42644ad5aa4c6524189812eb0819f05c4eef4c71ace90d822a990e87; ModelTransform: 394.487,394.487,0,0,0,0,0,0,0; Number of I/O: 48
U2 = CH224K: Type:Power Receiver Controller Protocol:PD 3.0 Number of Channels:- Output Power:100W Output Voltage:5V；20V；15V；12V；9V Voltage - Supply:4V~30V Voltage - Supply:4V~30V Operating Temperature:-40℃~+90℃ Operating Temperature:-40℃~+90℃ Features:Thermal Protect; Manufacturer: WCH(南京沁恒); Add into BOM: yes; ModelId: caddd54494d446ce85a816aa480d5ff10819f05c4eef4c71ace90d822a990e87; ModelTransform: 192.913,236.22,0,0,0,0,0,0,0; Protocol: PD 3.0; Output Power: 100W; Voltage - Supply: 4V~30V
U3 = BQ25798RQMR: The Chip Type:Charging IC Voltage - Supply:3.6V~24V Voltage - Supply:3.6V~24V Charge Current - Max:5A Type of Battery:Lithium Battery Number of Cells:1~4 Number of Cells:1~4 Operating Temperature:-40℃~+85℃ Operating Temperature:-40℃~+85℃ Battery Temperatu; Manufacturer: TI(德州仪器); Add into BOM: yes; ModelId: 359ccb1411cf4750b283dd43433afa970819f05c4eef4c71ace90d822a990e87; ModelTransform: 158.267,158.267,0,0,0,0,0,-0.197,0; Charge Current - Max: 5A; Number of Cells: 1~4; Battery Temperature Detection: Support; Supply Current (Iq): 17uA; Interface: I2C
U4 = TPS563201DDCR: Function:Step-down type Voltage - Supply:4.5V~17V Voltage - Supply:4.5V~17V Output Voltage:768mV~7V Output Voltage:768mV~7V Output Current:3A Frequency - Switching:580kHz Frequency - Switching:580kHz Operating Temperature:-40℃~+125℃@(TJ) Operating Tempera; Manufacturer: TI(德州仪器); Add into BOM: yes; ModelId: 1370be37a17e44418ae52e2b4cc1f5e50819f05c4eef4c71ace90d822a990e87; ModelName: SOT-23-6_L2.9-W1.6-H1.5-LS2.8-P0.95; ModelTransform: 110.73671,114.173,0,180,0,0,0.001,-0.003,0; Output Current: 3A; Frequency - Switching: 580kHz; Number of Outputs: 1; Topology: Buck; Quiescent Current: 380uA; Switch tube (built-in/external): Built-in; Output Type: Adjustable
U5 = TPS54202DDCR: Function:Step-down type Voltage - Supply:4.5V~28V Voltage - Supply:4.5V~28V Output Voltage:- Output Voltage:- Output Current:2A Frequency - Switching:500kHz Frequency - Switching:500kHz Operating Temperature:-40℃~+125℃@(TJ) Operating Temperature:-40℃~+125; Manufacturer: TI(德州仪器); Add into BOM: yes; ModelId: 1370be37a17e44418ae52e2b4cc1f5e50819f05c4eef4c71ace90d822a990e87; ModelName: SOT-23-6_L2.9-W1.6-H1.5-LS2.8-P0.95; ModelTransform: 110.236,113.364,0,90,0,0,0.0005,0.0005,0; Output Current: 2A; Frequency - Switching: 500kHz; Number of Outputs: 1; Topology: Buck; Quiescent Current: 45uA; Switch tube (built-in/external): Built-in; Output Type: Adjustable
U6 = W25Q32JVSSIQ_C82344: Interface:SPI Memory Size:32Mbit Clock Frequency:133MHz Voltage - Supply:2.7V~3.6V Voltage - Supply:2.7V~3.6V Standby Supply Current:10uA Program / Erase Cycles:100,000 cycles Write Cycle Time (tWC):- Page Programming Time (Tpp):3ms Block Erase Time(tBE):; Manufacturer: Winbond(华邦); Add into BOM: yes; ModelId: 7b3104f4a302484e875593c5ba7bd3db0819f05c4eef4c71ace90d822a990e87; ModelName: SOIC-8_L5.3-W5.3-H1.9-LS7.9-P1.27; ModelTransform: 208.661,311.25654,0,0,0,0,-0.0005,0.0005,0; Interface: SPI; Memory Size: 32Mbit; Clock Frequency: 133MHz; Standby Supply Current: 10uA; Page Programming Time (Tpp): 3ms; Block Erase Time(tBE): 120ms@(32KB); Data Retention - TDR (Year): 20 Years
U7 = APS6404L-3SQR-ZR: Manufacturer: Apmemory; Add into BOM: yes; ModelId: 2b35e1c3dcc44b77887d4f445b51370a0819f05c4eef4c71ace90d822a990e87; ModelName: USON-8_L2-W3-H0.6X0.5P; ModelTransform: 79.527,118.8974,0,0,0,0,-0.313,-1.1,0
U8 U9 = INA226AIDGSR: Number of Channels:- Vcm - Common Mode Voltage:0V~36V Vcm - Common Mode Voltage:0V~36V Gain:- Bandwidth:- Ib - Input Bias Current:100pA Vos - Input Offset Voltage:2.5uV Operating Temperature:-40℃~+125℃ Operating Temperature:-40℃~+125℃ Differential Voltage; Manufacturer: TI(德州仪器); Add into BOM: yes; ModelId: 875cf331c88d40d1aea94374997f39b10819f05c4eef4c71ace90d822a990e87; ModelName: MSOP-10_L3.0-W3.0-H1.1-LS5.0-P0.50; ModelTransform: 118.11,196.85,0,0,0,0,0,0,0; Vcm - Common Mode Voltage: 0V~36V; Ib - Input Bias Current: 100pA; Vos - Input Offset Voltage: 2.5uV; Differential Voltage: ±40V; Single Supply: 2.7V~5.5V; Quiescent Current: 330uA; Input Offset Voltage Drift(Vos TC): 0.1uV/℃; Common Mode Rejection Ratio (CMRR): 140dB
U10 = LPS22HBTR: Pressure range:26Kpa~1.26bar Pressure range:26Kpa~1.26bar Voltage - Supply:1.7V~3.6V Voltage - Supply:1.7V~3.6V Standby Current:1uA Interface:SPI；I2C Module:No Absolute Accuracy:0.1hpa Relative Accuracy:0.1hpa Features:On-chip temperature compensation；Int; Manufacturer: ST(意法半导体); Add into BOM: yes; ModelId: 02ad9adc3b5149f0a499482c2afb62890819f05c4eef4c71ace90d822a990e87; ModelName: HLGA-10L_L2.0-W2.0-H0.8-P0.5-LPS22HBTR; ModelTransform: 78.74,78.74,0,0,0,0,0,0.195,0; Standby Current: 1uA; Module: No; Absolute Accuracy: 0.1hpa
U11 = BME680: Pressure range:30Kpa~1.1bar Pressure range:30Kpa~1.1bar Voltage - Supply:1.71V~3.6V Voltage - Supply:1.71V~3.6V Standby Current:150nA Interface:SPI；I2C Module:- Absolute Accuracy:0.6hpa Relative Accuracy:0.12hpa Features:Standby mode；Integrated ADC and di; Manufacturer: Bosch(博世); Add into BOM: yes; ModelId: b8c5a93640fd43cf889b444887718f200819f05c4eef4c71ace90d822a990e87; ModelName: LGA-8_L3.0-W3.0-H0.9-P0.80-TR; ModelTransform: 118.11,118.11,0,0,0,0,0,0,0; Standby Current: 150nA; Absolute Accuracy: 0.6hpa; Temperature Coefficient of Offset(TCO): 1.3pa/K
U13 = LIS3MDLTR: Magnetic Sensing Range(X,Y):±1.2mT；±1.6mT；±4Gs；±8Gs Magnetic Sensing Range(X,Y):±1.2mT；±1.6mT；±4Gs；±8Gs Magnetic Sensing Range(Z):±4Gs；±1.2mT；±8Gs；±1.6mT Magnetic Sensing Range(Z):±4Gs；±1.2mT；±8Gs；±1.6mT Output bit:16bit Interface Type:SPI；I2C Voltage - S; Manufacturer: ST(意法半导体); Add into BOM: yes; ModelId: 08d0e00f89c34818888f739e33f114130819f05c4eef4c71ace90d822a990e87; ModelName: LGA-12_L2.0-W2.0-H1.0-P0.50; ModelTransform: 78.74,78.74,0,90,0,0,0,0.001,0; Output bit: 16bit; Voltage - Supply: 1.9V~3.6V; Current - Supply: 270uA；1uA；40uA
U14 = LSM9DS1TR: Accelerometer Sensing Axis:X,Y,Z Acceleration Measurement Range (MAX):±16g Acceleration Measurement Range (MAX):±16g Gyroscope Sensing Axis:X,Y,Z Gyroscope Measurement Range (MAX):±2000dps Gyroscope Measurement Range (MAX):±2000dps Sensor Type:IMU (accele; Manufacturer: ST(意法半导体); Add into BOM: yes; ModelId: 06729e712fbf436e90dfd5c95b7315ee0819f05c4eef4c71ace90d822a990e87; ModelTransform: 137.795,118.11,0,0,0,0,0,0,0; Accelerometer Sensing Axis: X,Y,Z; Acceleration Measurement Range (MAX): ±16g; Sensor Type: IMU (accelerometer + gyroscope); Output Bits: 16bit; Interface: I2C；SPI; Voltage - Supply: 1.9V~3.6V
U15 = BNO055: Accelerometer Sensing Axis:X,Y,Z Acceleration Measurement Range (MAX):±16g Acceleration Measurement Range (MAX):±16g Gyroscope Sensing Axis:X,Y,Z Gyroscope Measurement Range (MAX):±2000dps Gyroscope Measurement Range (MAX):±2000dps Sensor Type:IMU (accele; Manufacturer: Bosch(博世); Add into BOM: yes; ModelId: 2256a7a8c01e4b8c876389a77bde68f70819f05c4eef4c71ace90d822a990e87; ModelName: LGA-28_L5.2-W3.8-H1.2-P0.50-BL; ModelTransform: 204.724,149.606,0,90,0,0,-0.004,0.004,0; Accelerometer Sensing Axis: X,Y,Z; Acceleration Measurement Range (MAX): ±16g; Sensor Type: IMU (accelerometer + gyroscope); Output Bits: 14bit；16bit; Interface: UART；I2C; Voltage - Supply: 2.4V~3.6V; Standby Current: 40uA
U16 U22 = EVQ-Q2P02W: Circuit:SPST Actuator Style:Round Button Operating Force:1.6N Mounting Type:Surface Mount,Vertical Length:6.5mm Width:6mm Switch Height:2.5mm Contact Current:20mA Voltage Rating:15V With Lamp:- IP Rating:- Termination Style:J-Lead Life:1,000,000 cycles Op; Manufacturer: PANASONIC(松下); Add into BOM: yes; ModelId: fe986412e056403e95cd55841a82b76e0819f05c4eef4c71ace90d822a990e87; ModelTransform: 260.751,240.337,0,0,0,0,-0.001,0,0; Circuit: SPST; Operating Force: 1.6N; Switch Height: 2.5mm; Contact Current: 20mA; Voltage Rating: 15V
U17 = IM63D135AXTMA1: Direction:Omnidirectional Voltage - Supply:1.8V Voltage - Supply:1.8V Current Consumption:1.1mA~1.4mA Current Consumption:1.1mA~1.4mA S/N Ratio:63.5dB Sensitivity:-41dB Sensitivity:-41dB Length:3.5mm Width:2.65mm Height:0.98mm Operating Temperature:-40℃~+; Manufacturer: Infineon(英飞凌); Add into BOM: yes; ModelId: d3258170ac2d45d5985ecf8dc254410c0819f05c4eef4c71ace90d822a990e87; ModelTransform: 104.3305,137.795,0,0,0,0,0,2.402,0; Voltage - Supply: 1.8V; S/N Ratio: 63.5dB; Sensitivity: -41dB
U18 = ADAU1450WBCPZ-RL: Operating Temperature Range:-40℃~+105℃ Operating Temperature Range:-40℃~+105℃; Manufacturer: ADI(亚德诺); Add into BOM: yes; ModelId: e0591baa79fb4cafa64304a2951a30980819f05c4eef4c71ace90d822a990e87; ModelName: LFCSP-72_L10.0-W9.8-H1.0-P0.50; ModelTransform: 394.487,386.6134,0,0,0,0,-0.591,0.392,0
U19 U23-U30 = B3B-XH-A(LF)(SN): Pins Structure:1x3P Pitch:2.5mm Mounting Type:Through Hole Reference Series:XH Number of Pins:3P Number of Rows:1 Number of PINs Per Row:3 Row Spacing:- Current Rating:3A Contact Material:Brass Contact Plating:Tin Operating Temperature:-25℃~+85℃ Operating; Manufacturer: JST; Add into BOM: yes; ModelId: 5bef03a823d44d6d8bbe2419212192340819f05c4eef4c71ace90d822a990e87; ModelTransform: 393.7,226.3775,0,0,0,0,-0.005,-18.465,-125.984; Pins Structure: 1x3P; Pitch: 2.5mm; Reference Series: XH; Number of PINs Per Row: 3; Current Rating: 3A; Voltage Rating: 250V; Plastic Material: PA66; Flame Retardant Rating: UL94V-0; Supplementary Features: K Pin; Z-Height of the Board: 7mm; X-Length of Bottom Edge on Board (Spacing Line): 9.9mm; Y-Width of Bottom Edge on Board: 5.75mm
U20 U31 U32 = 2.54-1*4: Pin Structure:1x4P Pitch:2.54mm Circluar Pins/Square Pins:Pin Header Mounting Type:Through Hole Number of Rows:1 Number of Pins:4P Current Rating:2.5A Length of Mating Pin:6mm Insulation Height:2.54mm Length of End Connection Pin:3mm Contact Material:Bras; Manufacturer: ZHOURI(洲日); Add into BOM: yes; ModelId: e2e03939c192453cba872779c0cb63900819f05c4eef4c71ace90d822a990e87; ModelTransform: 400.039,100,0,0,0,0,0,0,-118.11; Pin Structure: 1x4P; Pitch: 2.54mm; Current Rating: 2.5A
U21 = HX PM1.27-2x3P ZC: Holes Structure:2x3P Pitch:1.27mm Row Spacing:1.27mm Circular Hole / Square Hole:Square Hole Mounting Type:Through Hole Number of Rows:2 Number of Positions:6P Current Rating:1A Voltage Rating (Max):500V Holes Direction:Top Insulation Height:4.3mm Contact; Manufacturer: hanxia(韩下); Add into BOM: yes; Holes Structure: 2x3P; Pitch: 1.27mm; Number of Positions: 6P; Current Rating: 1A; Voltage Rating (Max): 500V; Holes Direction: Top; PIN Length: 2.4mm
USBC1 = TYPE-C-31-M-12: Connector Type:Type-C Protocol Standard:- Gender:Female Mounting Type:Surface Mount, Right Angle Number of Contacts:16P Number of Ports:1 Current Rating-Power:5A Voltage Rating:20V Connect-Disconnect Life:10,000 cycles Length:7.35mm Operating Temperature:; Manufacturer: 韩国韩荣; Add into BOM: yes; ModelId: 8421221a464047838322348b3a9debc30819f05c4eef4c71ace90d822a990e87; ModelTransform: 351.9678,311.023,0,180,0,0,0,-43.307,-33.465; Connector Type: Type-C; Gender: Female; Number of Contacts: 16P; Number of Ports: 1; Current Rating-Power: 5A; Voltage Rating: 20V
X1 = X49SM12MSD2SC: Type:Crystal Oscillator Frequency:12MHz Normal temperature Frequency Tolerance:±20ppm Normal temperature Frequency Tolerance:±20ppm Load Capacitance:20pF Frequency Stability:±30ppm Frequency Stability:±30ppm Operating Temperature:-20℃~+70℃ Operating Tempe; Manufacturer: YXC(扬兴晶振); Add into BOM: yes; ModelId: c2ec6472aa1a474698dd1da780b3c79b0819f05c4eef4c71ace90d822a990e87; ModelName: HC-49S_L11.4-W1.8-H3.0-LS12.7; ModelTransform: 499.999,188.976,0,0,0,0,0,0,0; Normal temperature Frequency Tolerance: ±20ppm; Load Capacitance: 20pF; Frequency Stability: ±30ppm
X2 = NX3225GA-12.288MHz-STD-CRG-2: Type:- Frequency:- Load Capacitance:- Operating Temperature:- Operating Temperature:-; Manufacturer: NDK; Add into BOM: yes; ModelId: a2b47bc5d32f4dfd996128e047b549a00819f05c4eef4c71ace90d822a990e87; ModelTransform: 125.984,98.425,0,0,0,0,0,0,0
ZD1 = MMSZ5245B_C2126: Diode Configuration:1 Independent Zener Voltage(Nom):15V Reverse Leakage Current (Ir):100nA Zener Voltage(Range):14.25V~15.75V Zener Voltage(Range):14.25V~15.75V Pd - Power Dissipation:350mW Impedance(Zzt):16Ω Impedance(Zzk):600Ω Operating Junction Temper; Manufacturer: CJ(江苏长电/长晶); Add into BOM: yes; ModelId: 560a7cf99d0e44cb9af362aaf5d7923d0819f05c4eef4c71ace90d822a990e87; ModelTransform: 144.8816,62.992,0,0,0,0,0,0,0; Zener Voltage(Nom): 15V; Reverse Leakage Current (Ir): 100nA; Pd - Power Dissipation: 350mW; Impedance(Zzt): 16Ω; Impedance(Zzk): 600Ω; Operating Junction Temperature Range: -65℃~+150℃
